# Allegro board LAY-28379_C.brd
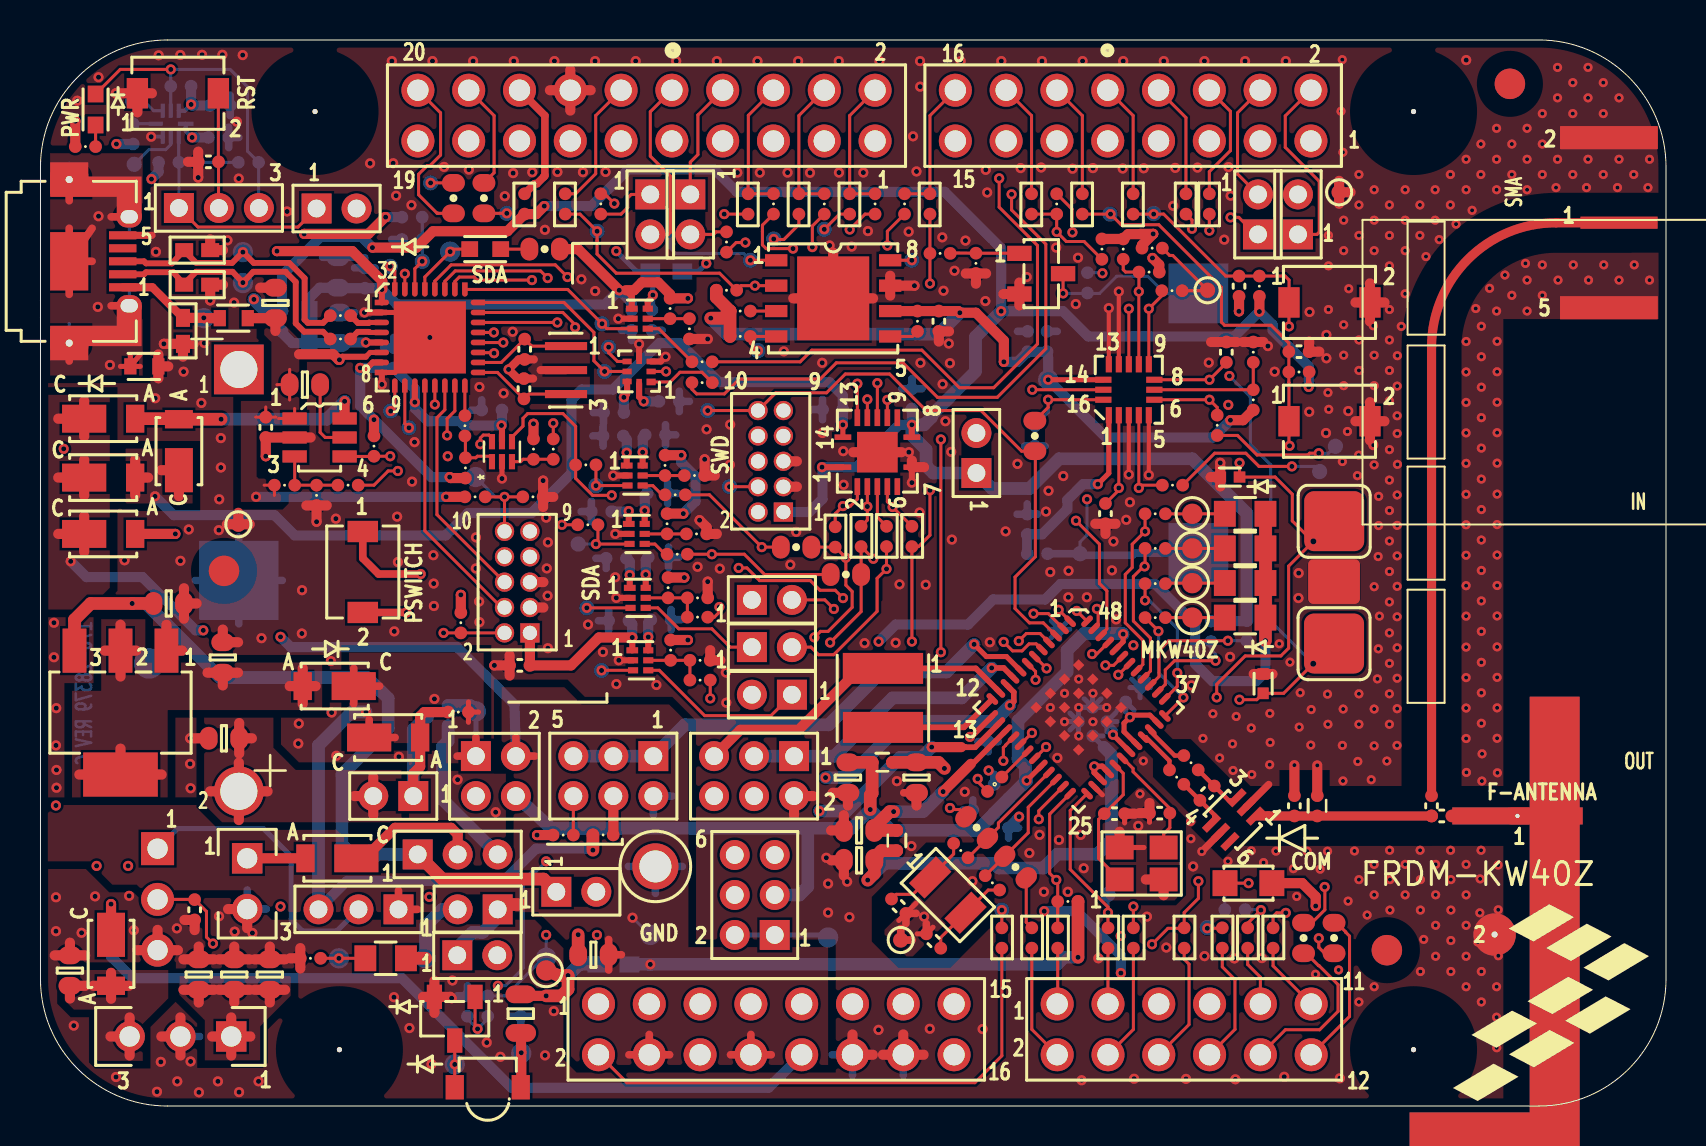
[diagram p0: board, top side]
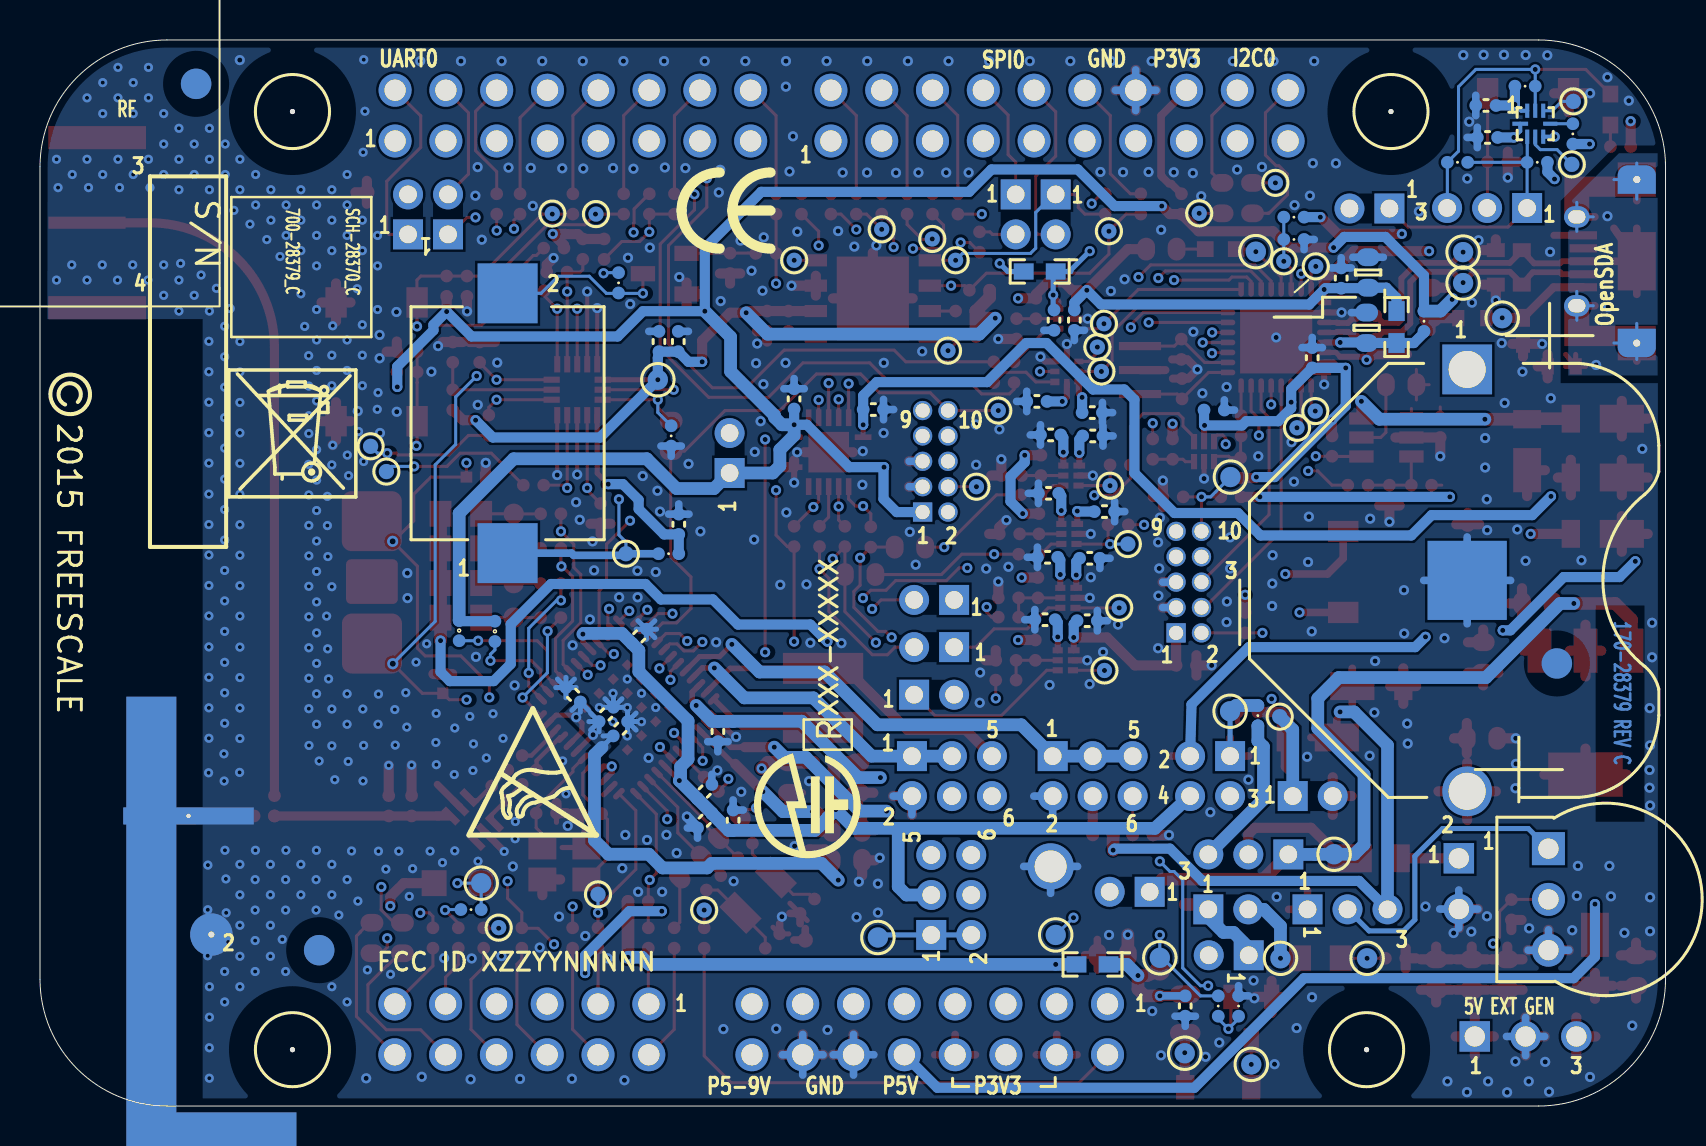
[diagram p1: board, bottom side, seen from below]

Outline 81.28 x 53.34 mm; copper layers: TOP, GND, INT_1, BOTTOM. Coordinates in mm from the lower left corner of the outline.
Outline path: 0,46.99 arc(1.86,51.48) 6.35,53.34 74.93,53.34 arc(79.42,51.48) 81.28,46.99 81.28,6.35 arc(79.42,1.86) 74.93,0 6.35,0 arc(1.86,1.86) 0,6.35 0,46.99

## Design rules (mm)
net group BALUN_100: nets N20694234 N20694236
net group RF: nets RF_N RF_P
net group USB_SI_CONN_D: nets N20299169 N20299247
net group USB_SI_D: nets SDA_USB_DN SDA_USB_DP
net group CLOCKS: nets SDA_EXTAL SWD_CLK_TGTMCU SWD_CLK_TGTMCU_BUF
net group POW: nets P5V0_SDA_USB_CONN_VBUS
nets with their own width: min track width 0.508; nets GND P3V3_SDA P5-9V_VIN P5-9V_VIN_VR

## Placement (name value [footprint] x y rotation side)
ANT1  F_Antenna  [F_ANTENNA_DIG528-2]  73.85 14.51 270 top
BT500  3003  [BATT_21X20MM]  9.92 36.86 270 bottom
BZ500  AST1109MLTRQ  [BUZZER_9P3X11P3_SMT]  57.9 34.16 0 bottom
C1  1000pF  [CC0402_25]  8.39 47.24 180 top
C2  1000pF  [CC0402_25]  59.93 41.02 270 top
C3  10uF  [CC0603_OV]  11.75 40.18 90 top
C6  0.1UF  [CC0402_25]  44.92 39.27 270 top
C9  1000pF  [CC0402_25]  62.93 37.74 0 top
C10  22PF  [CC0402_25]  24.21 37.86 270 top
C11  0.1UF  [CC0402_25]  59.3 37.72 90 top
C13  18PF  [CC0603_OV]  13.22 36.09 0 top
C15  22PF  [CC0402_25]  24.17 35.89 90 top
C21  0.1UF  [CC0402_25]  11.26 33.96 270 top
C22  0.1UF  [CC0402_25]  53.25 29.64 270 top
C25  10uF  [CC0603_OV]  6.41 25.15 0 top
C27  10uF  [CC0603_OV]  9.12 22.44 90 top
C31  0.1UF  [CC0402_25]  23.96 22.05 180 top
C32  1000pF  [CC0402_25]  7.71 9.82 270 top
C33  1.8pF  [CC0402_25]  62.7 15.02 90 top
C34  10PF  [CC0402_25]  69.56 15.02 90 top
C39  10uF  [CC0603_OV]  40.37 16.43 270 top
C40  10PF  [CC0402_25]  70.07 14.51 0 top
C41  11pF  [CC0402_25]  55.96 14.65 180 top
C42  0.6PF  [CC0402_25]  58.33 15.65 225 top
C43  10uF  [CC0603_OV]  9.17 18.4 180 top
C44  11pF  [CC0402_25]  53.7 14.63 0 top
C45  10uF  [CC0603_OV]  40.93 13.79 180 top
C46  12PF  [CC0402_25]  42.91 10 315 top
C47  12PF  [CC0402_25]  44.66 8.26 135 top
C48  2.2uF  [CC0603_OV]  27.65 7.57 180 top
C49  0.1UF  [CC0402_25]  24.02 5 270 bottom
C50  10uF  [CC0603_OV]  7.91 6.58 90 top
C51  10uF  [CC0603_OV]  9.69 6.58 90 top
C52  10uF  [CC0603_OV]  11.47 6.58 90 top
C53  10uF  [CC0603_OV]  1.47 6.78 90 top
C54  10uF  [CC0603_OV]  40.93 12.29 180 top
C55  10uF  [CC0603_OV]  43.8 16.43 270 top
C500  0.1UF  [CC0402_25]  8.98 50.06 0 bottom
C501  0.1UF  [CC0402_25]  8.9 48.46 0 bottom
C502  10uF  [CC0603_OV]  14.87 41.71 90 bottom
C503  0.1UF  [CC0402_25]  30.58 39.32 270 bottom
C504  0.1UF  [CC0402_25]  16.22 41.43 90 bottom
C505  0.1UF  [CC0402_25]  29.56 39.32 270 bottom
C506  2.2uF  [CC0603_OV]  14.95 38.94 90 bottom
C507  0.1UF  [CC0402_25]  50.33 38.25 90 bottom
C508  4.7uF  [CC0402_25]  49.36 38.25 90 bottom
C509  1uF  [CC0402_25]  17.67 37.44 90 bottom
C510  0.1UF  [CC0402_25]  43.57 35.38 90 bottom
C511  0.1UF  [CC0402_25]  31.43 35.26 0 bottom
C512  0.1UF  [CC0402_25]  39.61 34.85 180 bottom
C513  0.1UF  [CC0402_25]  22.57 34.82 180 bottom
C514  0.1UF  [CC0402_25]  28.66 34.7 180 bottom
C515  0.1UF  [CC0402_25]  30.75 33.58 0 bottom
C516  0.1UF  [CC0402_25]  28.64 33.53 180 bottom
C517  0.1UF  [CC0402_25]  30.85 30.66 0 bottom
C518  0.1UF  [CC0402_25]  28.05 29.74 180 bottom
C519  0.1UF  [CC0402_25]  49.34 29.11 90 bottom
C520  0.1UF  [CC0402_25]  30.9 27.46 0 bottom
C521  0.1UF  [CC0402_25]  28.79 27.41 180 bottom
C522  0.1UF  [CC0402_25]  31.03 24.33 0 bottom
C523  0.1UF  [CC0402_25]  28.92 24.28 180 bottom
C524  0.1UF  [CC0402_25]  51.32 23.5 135 bottom
C525  12PF  [CC0402_25]  52.26 18.88 135 bottom
C526  12PF  [CC0402_25]  54.62 20.58 45 bottom
C527  12PF  [CC0402_25]  52.97 19.59 135 bottom
C528  0.1UF  [CC0402_25]  48.04 15.73 135 bottom
C529  0.1UF  [CC0402_25]  46.62 14.3 90 bottom
C530  0.1UF  [CC0402_25]  48.04 14.27 315 bottom
C531  1uF  [CC0402_25]  47.38 18.74 270 bottom
D1  RED  [LED_0603]  2.76 49.86 90 top
D2  LED GREEN  [LED_0603]  22.24 42.88 180 top
D3  DFLS130L-7  [POWERDI-123_3MMX2MM]  3.04 34.39 0 top
D4  DFLS130L-7  [POWERDI-123_3MMX2MM]  6.92 32.66 90 top
D5  DFLS130L-7  [POWERDI-123_3MMX2MM]  3.04 31.45 0 top
D6  DFLS130L-7  [POWERDI-123_3MMX2MM]  3.04 28.63 0 top
D7  DFLS130L-7  [POWERDI-123_3MMX2MM]  14.81 21.01 180 top
D8  DFLS130L-7  [POWERDI-123_3MMX2MM]  17.29 18.44 0 top
D9  DFLS130L-7  [POWERDI-123_3MMX2MM]  14.95 12.4 180 top
D10  DFLS130L-7  [POWERDI-123_3MMX2MM]  3.53 7.72 270 top
D11  VSMB2948SL  [LED_RA_2P5X2P75_SM]  22.36 0.94 0 top
J1  CON_2x8_0.1"  [MTCONN_JT254F-D180-850-208-10D]  63.53 48.29 180 top
J2  CON_2x10_0.1"  [MTCONN_JT254F-D180-850-210-10D]  41.73 48.29 180 top
J3  CON_2x8_0.1"  [MTCONN_JT254F-D180-850-208-10D]  27.9 5.11 0 top
J4  CON_2x6_0.1"  [MTCONN_JT254F-D180-850-206-10D]  50.84 5.11 0 top
J5  SMA  [CON_SMA_EDGE_062]  78.93 44.2 90 top
J6  USB_MICRO_AB  [CON_MICROAB_10F_25_SM_RA]  1.54 42.27 0 top
J8  HDR_2X1  [HDR102_2MM]  46.8 31.67 270 top
J9  HDR 2X5  [HDR_5X2_FTSH_TH_NSP]  37.15 29.72 180 top
J11  HDR 2X5  [HDR_5X2_FTSH_TH_NSP]  24.47 23.67 180 top
J12  HDR 1X2  [SH_HDR102_2MM_BOTTOM]  35.57 25.32 180 top
J13  HDR 1X2  [SH_HDR102_2MM_BOTTOM]  35.57 22.96 180 top
J14  HDR 1X2  [SH_HDR102_2MM_BOTTOM]  37.57 20.58 0 top
J15  HDR_1X3  [HDR103_78MIL]  17.9 9.84 0 top
J16  HDR 2X3  [HDR203_TMM]  30.65 17.51 180 top
J17  HDR 2X3  [HDR203_TMM]  37.68 17.51 180 top
J18  HDR 2X2  [HDR202_TMM]  21.77 17.51 270 top
J19  HDR 1X2 TH  [HDR102]  10.34 12.4 0 top
J20  HDR_2X1  [HDR102_2MM]  22.86 9.84 0 top
J21  HDR_2X1  [HDR102_2MM]  20.84 7.54 180 top
J22  HDR 2X3  [HDR203_TMM]  36.72 8.56 90 top
J23  HDR_1X3  [HDR103_78MIL]  18.86 12.59 180 top
J24  HDR_1X3  [HDR103_78MIL]  6.92 44.93 180 top
J25  HDR 1X2  [SH_HDR102_2MM_BOTTOM]  13.8 44.91 180 top
J26  HDR_1X3  [HDR103]  9.54 3.48 270 top
J27  HDR_2X1  [HDR102_2MM]  18.64 15.51 0 top
J28  HDR_2X1  [HDR102_2MM]  32.49 45.61 90 top
J29  HDR_2X1  [HDR102_2MM]  30.49 45.61 90 top
J30  HDR_2X1  [HDR102_2MM]  62.88 43.61 270 top
J31  HDR_2X1  [HDR102_2MM]  60.88 43.61 270 top
J33  HDR_2X1  [HDR102_2MM]  25.79 10.72 180 top
L1  330 OHM  [IND_1608]  9.66 39.42 0 top
L2  330 OHM  [IND_1608]  5.19 37.01 0 top
L3  10uH  [IND_VLS4012E]  42.13 20.42 270 top
L4  2.4nH  [IND_0402]  63.84 15.02 90 top
L5  10nH  [IND_0402]  42.09 17.2 0 top
L6  10nH  [IND_0402]  42.81 13.28 270 top
LED1  RED  [LED2_0805]  60.24 29.63 90 top
LED2  RED  [LED2_0805]  60.24 27.9 90 top
LED3  RED  [LED2_0805]  60.24 26.17 90 top
LED4  RED  [LED2_0805]  60.24 24.44 90 top
LED5  BLUE  [LED2_2P34_2P1X1P25]  60.4 11.15 0 top
LED6  GREEN  [LED2_0805]  17.26 7.39 90 top
NOREF  -  []  52.33 15.63 90 top
NOREF#2  -  []  4.46 3.48 0 top
NOREF#3  -  []  -381.97 185.27 0 top
NOREF#4  -  []  62.55 28.51 90 top
NOREF#5  -  []  54.92 37.11 0 top
NOREF#6  -  []  5.79 48.52 0 top
NOREF#7  -  []  47.6 20.37 0 top
NOREF#8  -  []  79.81 7.46 0 top
NOREF#9  -  []  50.49 20.65 90 top
NOREF#10  -  []  6.52 48.5 0 top
NOREF#11  -  []  52.33 15.63 90 top
NOREF#12  -  []  6.71 48.53 90 top
NOREF#13  -  []  50.49 20.65 90 top
NOREF#14  -  []  -16.59 -36.7 0 top
NOREF#15  -  []  -408 -339.88 0 top
NOREF#16  -  []  46.96 19.94 0 top
NOREF#17  -  []  46.96 19.94 0 top
NOREF#18  -  []  51.91 14.99 90 top
NOREF#19  -  []  341.11 -159.27 0 top
NOREF#20  -  []  51.91 14.99 90 top
NOREF#21  -  []  48.3 18.81 0 top
NOREF#22  -  []  70.32 0.01 90 top
NOREF#23  -  []  42.13 18.95 90 top
NOREF#24  -  []  40.46 18.37 90 top
NOREF#25  -  []  52.69 15.98 90 top
NOREF#26  -  []  22.36 0.36 90 top
NOREF#27  -  []  24.01 0.94 90 top
NOREF#28  -  []  -36.81 -140.12 90 top
NOREF#29  -  []  40.07 18.75 0 top
NOREF#30  -  []  49.79 19.94 90 top
NOREF#31  -  []  70.62 0.25 0 top
NOREF#32  -  []  54.92 37.11 0 top
NOREF#33  -  []  48.3 18.81 0 top
NOREF#34  -  []  20.71 0.94 0 top
NOREF#35  -  []  57.9 27.66 90 top
NOREF#36  -  []  49.79 19.94 90 top
NOREF#37  -  []  47.6 19.52 0 top
NOREF#38  -  []  55.42 34.56 90 top
NOREF#39  -  [unnamed#2]  9.18 26.78 0 top
NOREF#40  -  [unnamed#2]  73.47 51.15 0 top
NOREF#41  -  []  6.12 48.5 90 top
NOREF#42  -  []  32.33 11.99 0 top
NOREF#43  -  []  62.55 39.81 0 top
NOREF#44  -  []  52.92 31.34 0 top
NOREF#45  -  []  47.6 19.52 0 top
NOREF#46  -  []  47.6 20.37 0 top
NOREF#47  -  []  4.46 3.48 0 top
NOREF#48  -  []  55.42 34.56 90 top
NOREF#49  -  []  52.92 31.35 0 top
NOREF#50  -  []  4.46 3.48 0 top
NOREF#51  -  []  51.48 15.63 90 top
NOREF#52  -  []  53.42 37.11 0 top
NOREF#53  -  []  318.09 -153.04 0 top
NOREF#54  -  []  0 41.47 0 top
NOREF#55  -  []  52.69 15.98 90 top
NOREF#56  -  []  55.69 35.34 90 top
NOREF#57  -  [unnamed#2]  67.32 7.8 0 top
NOREF#58  -  []  78.89 16.29 0 top
NOREF#59  -  []  151.38 59.85 0 top
NOREF#60  -  []  -36.81 -113.45 0 top
NOREF#61  -  []  51.48 15.63 90 top
NOREF#62  -  []  21.11 0.41 0 top
NOREF#63  -  []  53.14 36.34 0 top
NOREF#64  -  []  55.92 31.34 90 top
NOREF#65  -  []  345 -146.74 0 top
NOREF#66  -  []  -71.81 -129.47 0 top
NOREF#67  -  [unnamed#2]  13.73 49.76 180 bottom
NOREF#68  -  [unnamed#2]  73.47 51.15 180 bottom
NOREF#69  -  []  225.55 -29.24 90 bottom
NOREF#70  -  []  74.49 -17.35 0 bottom
NOREF#71  -  [unnamed#2]  67.32 7.8 180 bottom
NOREF#72  -  []  40.28 12.4 90 bottom
NOREF#73  -  []  91.82 39.52 180 bottom
NOREF#74  -  [unnamed#2]  68.66 49.76 180 bottom
NOREF#75  -  []  106.28 -52.14 270 bottom
NOREF#76  -  []  54.61 5.51 180 bottom
NOREF#77  -  [unnamed#2]  14.95 2.82 180 bottom
NOREF#78  -  []  77.85 10.86 180 bottom
NOREF#79  -  [unnamed#2]  5.43 22.14 180 bottom
NOREF#80  -  []  54.66 12.88 180 bottom
NOREF#81  -  []  85.94 -20.8 180 bottom
NOREF#82  -  [unnamed#2]  68.66 2.82 180 bottom
NOREF#83  -  []  47.36 44.81 90 bottom
NOREF#84  -  []  71.84 30.48 180 bottom
Q1  MMBT3904LT1G  [SOT23]  50.04 41.65 270 top
Q2  MMBT3904LT1G  [SOT23]  20.71 4.37 180 top
R1  100  [RC0402_25]  2.25 48.01 0 top
R3  0  [RC0402_25]  39.19 45.14 90 top
R4  0  [RC0402_25]  41.73 45.14 90 top
R5  0  [RC0402_25]  43.21 45.14 90 top
R7  0  [RC0402_25]  50.81 45.14 270 top
R8  0  [RC0402_25]  36.65 45.14 90 top
R10  220  [RC0603_OV]  25.21 42.88 180 top
R12  4.7K  [RC0402_25]  44.98 42.66 0 top
R13  10.0K  [RC0402_25]  54.14 42.88 270 top
R14  47K  [RC0402_25]  46.77 42.16 270 top
R16  10.0K  [RC0402_25]  34.3 40.82 0 top
R17  10.0K  [RC0402_25]  60.95 41.02 90 top
R18  0  [RC0402_25]  56.58 40.79 0 top
R19  4.7K  [RC0402_25]  31.48 39.9 270 top
R20  10.0K  [RC0402_25]  34.99 39.78 0 top
R21  33  [RC0402_25]  15 39.55 0 top
R22  10.0K  [RC0402_25]  43.85 39.27 90 top
R23  10.0K  [RC0402_25]  32.45 38.89 270 top
R24  10.0K  [RC0402_25]  34.99 38.51 0 top
R25  33  [RC0402_25]  15 38.38 0 top
R26  10.0K  [RC0402_25]  62.93 36.73 180 top
R27  1K  [RC0402_25]  33.08 37.24 0 top
R28  1K  [RC0402_25]  33.08 36.2 180 top
R29  10.0K  [RC0402_25]  60.64 35.33 90 top
R30  0  [RC0402_25]  58.84 34.06 270 top
R31  0  [RC0402_25]  21.22 34.04 90 top
R32  0  [RC0603_OV]  49.72 33.53 270 top
R33  10.0K  [RC0402_25]  16.68 33.02 270 top
R34  10.0K  [RC0402_25]  24.65 32.87 90 top
R35  0  [RC0402_25]  25.64 32.87 90 top
R36  0  [RC0402_25]  27.27 32.08 0 top
R37  4.7K  [RC0402_25]  31.23 32.05 270 top
R38  10.0K  [RC0402_25]  21.25 31.93 90 top
R39  10.0K  [RC0402_25]  32.7 31.55 0 top
R40  10.0K  [RC0402_25]  12.2 31.06 0 top
R41  1K  [RC0402_25]  15.38 31.06 180 top
R42  0  [RC0402_25]  56.6 31.06 0 top
R43  1K  [RC0402_25]  31.74 30.58 0 top
R44  15K  [RC0402_25]  13.8 30.56 270 top
R45  0  [RC0603_OV]  63.16 8.41 270 top
R46  4.7K  [RC0402_25]  21.73 30.48 0 top
R47  10.0K  [RC0402_25]  24.63 30.48 0 top
R48  330  [RC0402_25]  55.74 29.63 180 top
R49  4.7K  [RC0402_25]  31.33 29.13 270 top
R50  0  [RC0402_25]  27.37 29.08 0 top
R51  10.0K  [RC0402_25]  32.8 28.63 0 top
R52  0  [RC0603_OV]  37.78 27.97 0 top
R53  330  [RC0402_25]  55.74 27.9 180 top
R54  0  [RC0603_OV]  64.68 8.41 270 top
R55  1K  [RC0402_25]  31.84 27.61 0 top
R56  0  [RC0603_OV]  40.27 26.59 0 top
R57  330  [RC0402_25]  55.74 26.14 180 top
R59  4.7K  [RC0402_25]  31.38 25.93 270 top
R60  10.0K  [RC0402_25]  32.85 25.43 0 top
R61  0  [RC0402_25]  32.85 24.46 180 top
R62  330  [RC0402_25]  55.74 24.44 180 top
R63  10.0K  [RC0402_25]  21.02 24.18 270 top
R64  4.7K  [RC0402_25]  31.51 22.81 270 top
R65  10.0K  [RC0402_25]  32.98 22.3 0 top
R66  0  [RC0402_25]  32.98 21.31 180 top
R67  5K  [POT3_3352T]  5.85 12.88 270 bottom
R68  0  [RC0402_25]  47.71 16.1 225 top
R69  0  [RC0402_25]  57.53 17.18 315 top
R70  0  [RC0402_25]  56.81 16.46 315 top
R71  0  [RC0603_OV]  46.81 13.93 315 top
R72  0  [RC0402_25]  28.13 13.56 0 top
R73  0  [RC0402_25]  20.89 19.71 0 top
R74  0  [RC0402_25]  46.02 12.78 135 top
R75  0  [RC0402_25]  20.38 19.53 90 bottom
R76  0  [RC0603_OV]  48.75 11.96 315 top
R77  0  [RC0402_25]  47.6 11.17 315 top
R78  0  [RC0402_25]  51.37 10.24 180 top
R79  27K  [RC0402_25]  21.35 5 90 bottom
R80  1.5K  [RC0402_25]  22.36 5 270 bottom
R81  330  [RC0402_25]  13.5 7.39 180 top
R82  18.2  [RC0805_OV]  24.02 4.62 270 top
R83  0  [RC0402_25]  28.02 45.14 270 top
R84  0  [RC0402_25]  34.3 43.23 90 top
R85  102K  [RC0402_25]  26.14 13.56 180 top
R87  0  [RC0603_OV]  22.17 45.43 90 top
R88  0  [RC0603_OV]  20.65 45.43 90 top
R500  180K  [RC0402_25]  7.02 51.03 180 bottom
R501  4.7K  [RC0402_25]  4.64 48.64 270 bottom
R502  0  [RC0402_25]  10.4 47.22 0 bottom
R503  10.0K  [RC0402_25]  6.41 47.22 0 bottom
R504  4.7K  [RC0402_25]  18.58 44.48 0 bottom
R505  10.0K  [RC0402_25]  18.58 43.36 180 bottom
R506  10.0K  [RC0402_25]  49.72 33.53 270 bottom
R507  0  [RC0402_25]  49.85 27.64 0 bottom
R508  10.0K  [RC0402_25]  60.32 23.79 270 bottom
R509  10.0K  [RC0402_25]  58.53 23.75 270 bottom
R510  10.0K  [RC0402_25]  53.07 42.88 270 top
R511  330  [RC0402_25]  59.73 9.83 0 bottom
R512  1K  [RC0402_25]  52.35 41.19 270 bottom
R513  10.0K  [RC0402_25]  55.59 42.93 0 top
SH3  0  [SH0402]  24.21 45.14 90 top
SH4  0  [SH0402]  26.24 45.14 90 top
SH7  0  [SH0402]  35.38 45.14 90 top
SH8  0  [SH0402]  37.92 45.14 90 top
SH9  0  [SH0402]  40.46 45.14 90 top
SH10  0  [SH0402]  44.48 45.14 90 top
SH11  0  [SH0402]  49.56 45.14 90 top
SH12  0  [SH0402]  52.1 45.14 90 top
SH13  0  [SH0402]  54.64 45.14 90 top
SH14  0  [SH0402]  57.28 45.14 90 top
SH15  0  [SH0402]  58.45 45.14 90 top
SH18  0  [RC0402_25]  55.43 41.73 0 top
SH19  0  [RC0402_25]  60.64 37.72 90 top
SH20  0  [SH0402]  41.03 28.5 270 top
SH21  0  [SH0402]  42.3 28.5 270 top
SH22  0  [SH0402]  43.57 28.5 270 top
SH23  0  [SH0402]  39.74 28.47 270 top
SH24  0  [SH0402]  48.07 8.41 270 top
SH25  0  [SH0402]  49.57 8.41 270 top
SH26  0  [SH0402]  50.86 8.41 270 top
SH27  0  [SH0402]  53.38 8.41 270 top
SH28  0  [SH0402]  54.65 8.41 270 top
SH29  0  [SH0402]  57.19 8.41 270 top
SH30  0  [SH0402]  59.09 8.41 270 top
SH31  0  [SH0402]  60.36 8.41 270 top
SH33  0  [SH0402]  61.63 8.41 270 top
SH500  0  [SH0603]  31.29 41.76 0 bottom
SH501  0  [SH0603]  13.45 38.98 270 bottom
SH502  0  [RC0402_25]  12.08 39.27 90 bottom
SH503  0  [SH0603]  28.65 7.09 0 bottom
SW1  3x3mm  [ELECTRODE_SQ_3MM]  64.68 23.14 0 top
SW2  3x3mm  [ELECTRODE_SQ_3MM]  64.69 29.26 0 top
SW3  TL1015AF160QG  [SW2_SPST_4X3_SM]  64.45 34.26 0 top
SW4  TL1015AF160QG  [SW2_SPST_4X3_SM]  64.45 40.21 0 top
SW5  TL1015AF160QG  [SW2_SPST_4X3_SM]  16.12 26.72 270 top
SW6  TL1015AF160QG  [SW2_SPST_4X3_SM]  6.87 50.67 0 top
TP2  -  [TPAD_030]  64.94 45.72 0 top
TP3  -  [TPAD_040]  10.12 42.73 180 bottom
TP4  -  [TPAD_040]  10.12 41.18 180 bottom
TP14  -  [TPAD_030]  58.36 40.82 270 top
TP19  -  [TPAD_030]  64.75 33.01 270 bottom
TP20  -  [TPAD_030]  63.96 31.74 270 bottom
TP21  -  [TPAD_040]  57.59 29.63 180 top
TP22  -  [TPAD_030]  9.89 29.11 0 top
TP25  -  [TPAD_040]  57.59 27.9 270 top
TP26  -  [TPAD_040]  57.59 26.16 270 top
TP28  -  [TPAD_040]  57.59 24.44 180 top
TP29  -  [TPAD_030]  19.29 19.48 180 bottom
TP30  -  [TPAD_040]  21.77 19.75 0 bottom
TP31  TESTLOOP_BLACK  [TP_TH_063]  30.75 11.99 0 top
TP36  -  [TPAD_030]  43.01 8.31 0 top
TP500  -  [TPAD_030]  4.61 50.27 0 bottom
TP501  -  [TPAD_030]  4.69 47.12 0 bottom
TP502  -  [TPAD_030]  55.66 44.65 180 bottom
TP503  -  [TPAD_030]  53.48 44.63 180 bottom
TP504  -  [TPAD_030]  27.83 43.77 0 bottom
TP505  -  [TPAD_030]  39.19 43.87 180 bottom
TP506  -  [TPAD_030]  36.66 43.38 180 bottom
TP507  -  [TPAD_040]  20.49 42.75 180 bottom
TP508  -  [TPAD_030]  43.57 42.32 0 bottom
TP509  -  [TPAD_030]  35.5 42.32 0 bottom
TP510  -  [TPAD_030]  19.09 42.27 180 bottom
TP511  -  [TPAD_030]  17.49 42.01 0 bottom
TP513  -  [TPAD_040]  8.17 39.42 180 bottom
TP514  -  [TPAD_030]  28.08 39.14 180 bottom
TP515  -  [TPAD_030]  28.41 37.97 0 bottom
TP516  -  [TPAD_030]  35.88 37.8 0 bottom
TP517  -  [TPAD_030]  28.21 36.75 0 bottom
TP518  -  [TPAD_040]  50.39 36.34 270 bottom
TP519  -  [TPAD_030]  33.36 34.8 90 bottom
TP520  -  [TPAD_030]  17.51 34.77 180 bottom
TP521  -  [TPAD_030]  18.43 33.93 180 bottom
TP522  -  [TPAD_030]  27.77 31.04 180 bottom
TP523  -  [TPAD_030]  34.46 30.99 180 bottom
TP524  -  [TPAD_040]  21.76 31.47 180 bottom
TP525  -  [TPAD_030]  26.89 28.12 180 bottom
TP526  -  [TPAD_030]  51.98 27.64 180 bottom
TP528  -  [TPAD_030]  27.32 24.93 180 bottom
TP529  -  [TPAD_030]  28.05 21.79 180 bottom
TP530  -  [TPAD_040]  16.57 12.6 180 bottom
TP531  -  [TPAD_040]  59.22 11.15 180 bottom
TP532  -  [TPAD_030]  53.38 10.59 180 bottom
TP533  -  [TPAD_040]  39.38 8.43 180 bottom
TP534  -  [TPAD_040]  30.49 8.56 180 bottom
TP535  -  [TPAD_040]  25.29 7.42 180 bottom
TP536  -  [TPAD_040]  19.25 7.39 0 bottom
TP537  -  [TPAD_040]  14.92 7.39 0 bottom
TP538  -  [TPAD_040]  24.04 2.64 180 bottom
TP539  -  [TPAD_040]  20.71 2.08 180 bottom
TP540  -  [TPAD_030]  23.32 44.67 180 bottom
TP541  -  [TPAD_030]  58.34 8.93 180 bottom
TP542  -  [TPAD_030]  19.51 46.19 180 bottom
TP543  -  [TPAD_030]  48.07 9.8 180 bottom
TP544  -  [TPAD_040]  25.29 6.78 90 top
TVS1  PGB2010402KRHF  [DIODE_0402]  59.47 31.47 180 top
TVS2  PGB2010402KRHF  [DIODE_0402]  61.14 21.13 90 top
U1  0402ESDA-MLP  [0402_MLP]  7.84 42.82 0 top
U2  0402ESDA-MLP  [0402_MLP]  7.84 41.1 0 top
U4  AT45DB021E  [DFN8_1P27_6X5MM_3P6X4P2]  39.64 40.41 0 top
U5  74LVCH1T45  [UDFN6_1X1P5MM]  29.98 39.4 0 top
U6  0402ESDA-MLP  [0402_MLP]  7.12 38.79 270 top
U7  MK20DX128VFM5  [QFN32_S142EP]  19.47 38.46 0 top
U8  74LVC2T45GM,125  [QFN8_1P6X1P6MM]  29.93 36.75 180 top
U9  FXOS8700CQ  [QFN5X3_0P5_3X3]  54.42 35.84 90 top
U10  MIC2005-0.8YM6  [SOT23-6_A]  13.96 33.45 0 top
U11  NLX2G14  [UDFN6_1P45X1_0P5MM]  23.08 32.74 90 top
U12  TXB0104  [QFN14_RGY]  41.85 32.72 0 top
U13  74LVCH1T45  [UDFN6_1X1P5MM]  29.73 31.55 0 top
U14  74LVCH1T45  [UDFN6_1X1P5MM]  29.83 28.63 0 top
U15  74LVCH1T45  [UDFN6_1X1P5MM]  29.88 25.43 0 top
U16  74LVCH1T45  [UDFN6_1X1P5MM]  30.01 22.3 0 top
U17  NCP1117ST33T3G  [SOT223]  4 19.69 180 top
U18  MKW40Z160VHT4  [MAPLGA64_7X7_0P5MM]  51.91 19.94 315 top
U500  NTSX2102GU8H  [XQFN8_1P45X1P25MM]  6.52 49.15 180 bottom
X1  8.00MHZ  [XTAL3_3P35X1P45_SM]  26.28 36.82 90 top
Y1  32MHZ  [XTLOSC4_3P2X2P5MM_SM]  55.06 12.14 0 top
Y2  32.768KHZ  [XTAL2-3P2X1P5-SM]  45.37 10.56 315 top
Z1  50/100 OHMS  [XFMR6_0P65_2X1]  59.65 14.33 135 top

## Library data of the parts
ANT1 = F_Antenna
BT500 = BATTERY_SKT_3V
BZ500 = BUZZER_PIEZO
C1 C2 C9-C11 C15 C22 C32 C33 C39 C41 C42 C44-C48 C50-C55 C506-C509 C525-C527 C531 = CAP_NP
C3 C6 C21 C25 C27 C31 C43 C49 C500-C505 C510-C524 C528-C530 = CAP_NP: tolerance: 10%
C13 C34 C40 = CAP_NP: tolerance: 5%
D1 D2 D11 LED1-LED6 = LED
D3-D10 = DIODE_SCHTKY
J1 J3 = CONN_2x8_MTCONN
J2 = CONN_2x10_MTCONN
J4 = CONN_2x6_MTCONN
J5 = SMB
J6 = MICRO_USB_CONN_10PIN
J8 J12-J14 J19-J21 J25 J27-J31 J33 = CONN_HDR_2X1
J9 J11 = CONN_HDR_5X2
J15 J23 J24 J26 = CONN_HDR_3X1
J16 J17 J22 = CONN_HDR_3X2
J18 = CONN_HDR_2X2
L1 L2 = BEAD
L3 = IND_FERRITE
L4-L6 = INDUCTOR
Q1 Q2 = NPN
R1 R13 R16 R17 R19 R20 R22 R24 R26 R29 R33 R37 R40 R44 R46 R49 R59 R64 R501 R504 R506 R508-R510 R513 = RES: tolerance: 1%
R3-R5 R7 R8 R10 R12 R14 R18 R21 R25 R27 R28 R30-R32 R35 R36 R41-R43 R45 R47 R48 R50 R52-R57 R61-R63 R66 R68-R85 R87 R88 R500 R505 R507 R511 R512 SH18 SH19 SH502 = RES
R23 R34 R38 R39 R51 R60 R65 R502 R503 = RES: tolerance: 5%
R67 = POT
SH3 SH4 SH7-SH15 SH20-SH31 SH33 SH500 SH501 SH503 = RES_SHORT-2
SW1 SW2 = ELECTRODE
SW3-SW6 = SW_SPNO_2P
TP2 TP14 TP19 TP20 TP22 TP29 TP31 TP36 TP500-TP506 TP508-TP511 TP514-TP517 TP519-TP523 TP525 TP526 TP528 TP529 TP532 TP540-TP543 = TESTLOOP
TP3 TP4 TP21 TP25 TP26 TP28 TP30 TP507 TP513 TP518 TP524 TP530 TP531 TP533-TP539 TP544 = TestLoop
TVS1 TVS2 U1 U2 U6 = DIODE_TVS_BIDIR
U4 = AT45DB021E_9P
U5 U13-U16 = 74LVCH1T45_6P
U7 = PK20DX128V_QFN_32P
U8 = 74LVC2T45GM_8P
U9 = FXOS8700CQ_QFN_16P
U10 = MIC2005-0.8YM6
U11 = NLU2GU04
U12 = TXB0104
U17 = LD1117AS18
U18 = MKW40Z160_MAPLGA64
U500 = NTSX2102GU8H_8P
X1 = XTAL_CS
Y1 = XTAL_13Y
Y2 = CRYSTAL
Z1 = 2450BL

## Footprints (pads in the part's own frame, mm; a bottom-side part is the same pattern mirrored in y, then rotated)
0402_MLP
  rect 0.9x0.7 smd: 1(-0.65,0) 2(0.65,0)
BATT_21X20MM
  rect 2.489x2.489 hole 1.854: 1(0,0)
  round 2.489 hole 1.854: 2(21.11,0)
  rect 3.96x3.96 smd: 3(10.555,0)
BUZZER_9P3X11P3_SMT
  rect 3x3 smd: 1(0,6.5) 2(0,-6.5)
CC0402_25
  round 0.635 smd: 1(-0.508,0) 2(0.508,0)
CC0603_OV
  oval 0.889x1.143 smd: 1(-0.762,0) 2(0.762,0)
CON_MICROAB_10F_25_SM_RA
  rect 1.372x0.406 smd: 1(2.575,-1.3) 2(2.575,-0.65) 3(2.575,0) 4(2.575,0.65) 5(2.575,1.3)
  oval 1.27x1.067 hole 0.864x0.66: 6(2.9,2.225) 7(2.9,-2.225)
  rect 1.905x2.921 smd: 8(-0.1,0)
  custom 0.356x0.356 hole 1.524x0.838: 9(-0.1,4.09) 10(-0.1,-4.09)
CON_SMA_EDGE_062
  rect 0.61x3.861 smd: 1(0,0)
  rect 1.143x4.877 smd: 2(4.255,0.508) 3(4.255,0.508) 4(-4.255,0.508) 5(-4.255,0.508)
DFN8_1P27_6X5MM_3P6X4P2
  rect 1.118x0.61 smd: 1(-2.85,1.905) 2(-2.85,0.635) 3(-2.85,-0.635) 4(-2.85,-1.905) 5(2.85,-1.905) 6(2.85,-0.635) 7(2.85,0.635) 8(2.85,1.905)
  rect 3.607x4.191 smd: 9(0,0)
DIODE_0402
  rect 0.584x0.559 smd: 1(-0.483,0) 2(0.483,0)
ELECTRODE_SQ_3MM
  custom 0.75x0.75 smd: 1(0,0)
F_ANTENNA_DIG528-2
  custom 0.212x0.212 hole 0.305: 1(0,0)
  custom 2.127x2.127 hole 0.305: 2(5.933,-1.144)
HDR102
  rect 1.524x1.524 hole 1.016: 1(0,0)
  round 1.524 hole 1.016: 2(0,-2.54)
HDR102_2MM
  rect 1.499x1.499 hole 0.889: 1(0,0)
  round 1.499 hole 0.889: 2(-2,0)
HDR103
  rect 1.524x1.524 hole 1.016: 1(0,0)
  round 1.524 hole 1.016: 2(0,-2.54) 3(0,-5.08)
HDR103_78MIL
  rect 1.499x1.499 hole 0.889: 1(0,0)
  round 1.499 hole 0.889: 2(-2,0) 3(-4,0)
HDR202_TMM
  rect 1.499x1.499 hole 0.889: 1(0,0)
  round 1.499 hole 0.889: 2(0,2) 3(2,0) 4(2,2)
HDR203_TMM
  rect 1.499x1.499 hole 0.889: 1(0,0)
  round 1.499 hole 0.889: 2(0,2) 3(2,0) 4(2,2) 5(4,0) 6(4,2)
HDR_5X2_FTSH_TH_NSP
  rect 0.965x0.965 hole 0.711: 1(0,0)
  round 0.965 hole 0.711: 2(1.27,0) 3(0,-1.27) 4(1.27,-1.27) 5(0,-2.54) 6(1.27,-2.54) 7(0,-3.81) 8(1.27,-3.81) 9(0,-5.08) 10(1.27,-5.08)
IND_0402
  round 0.635 smd: 1(-0.508,0) 2(0.508,0)
IND_1608
  rect 0.61x0.813 smd: 1(-0.7,0) 2(0.7,0)
IND_VLS4012E
  rect 1.549x4.013 smd: 1(-1.475,0) 2(1.475,0)
LED2_2P34_2P1X1P25
  rect 1.245x1.295 smd: A(1.172,0) C(-1.172,0)
LED2_0805
  rect 1.295x1.092 smd: A(0,-1.016) C(0,1.016)
LED_0603
  rect 0.838x0.787 smd: A(-0.775,0) C(0.775,0)
LED_RA_2P5X2P75_SM
  rect 0.914x1.219 smd: A(1.65,0) C(-1.65,0)
MAPLGA64_7X7_0P5MM
  oval 0.711x0.279 smd: 1(-3.35,2.75) 2(-3.35,2.25) 3(-3.35,1.75) 4(-3.35,1.25) 5(-3.35,0.75) 6(-3.35,0.25) 7(-3.35,-0.25) 8(-3.35,-0.75) 9(-3.35,-1.25) 10(-3.35,-1.75) 11(-3.35,-2.25) 12(-3.35,-2.75) 25(3.35,-2.75) 26(3.35,-2.25) 27(3.35,-1.75) 28(3.35,-1.25) 29(3.35,-0.75) 30(3.35,-0.25) 31(3.35,0.25) 32(3.35,0.75) 33(3.35,1.25) 34(3.35,1.75) 35(3.35,2.25) 36(3.35,2.75)
  oval 0.279x0.711 smd: 13(-2.75,-3.35) 14(-2.25,-3.35) 15(-1.75,-3.35) 16(-1.25,-3.35) 17(-0.75,-3.35) 18(-0.25,-3.35) 19(0.25,-3.35) 20(0.75,-3.35) 21(1.25,-3.35) 22(1.75,-3.35) 23(2.25,-3.35) 24(2.75,-3.35) 37(2.745,3.35) 38(2.25,3.35) 39(1.75,3.35) 40(1.25,3.35) 41(0.75,3.35) 42(0.25,3.35) 43(-0.25,3.35) 44(-0.75,3.35) 45(-1.25,3.35) 46(-1.75,3.35) 47(-2.25,3.35) 48(-2.75,3.35)
  rect 0.406x0.406 smd: 49(-1.5,1.5) 50(-0.5,1.5) 51(0.5,1.5) 52(1.5,1.5) 53(-1.5,0.5) 54(-0.5,0.5) 55(0.5,0.5) 56(1.5,0.5) 57(-1.5,-0.5) 58(-0.5,-0.5) 59(0.5,-0.5) 60(1.5,-0.5) 61(-1.5,-1.5) 62(-0.5,-1.5) 63(0.5,-1.5) 64(1.5,-1.5)
MTCONN_JT254F-D180-850-206-10D
  round 1.651 hole 1.067: 1(0,0) 2(0,-2.54) 3(2.54,0) 4(2.54,-2.54) 5(5.08,0) 6(5.08,-2.54) 7(7.62,0) 8(7.62,-2.54) 9(10.16,0) 10(10.16,-2.54) 11(12.7,0) 12(12.7,-2.54)
MTCONN_JT254F-D180-850-208-10D
  round 1.651 hole 1.067: 1(0,0) 2(0,-2.54) 3(2.54,0) 4(2.54,-2.54) 5(5.08,0) 6(5.08,-2.54) 7(7.62,0) 8(7.62,-2.54) 9(10.16,0) 10(10.16,-2.54) 11(12.7,0) 12(12.7,-2.54) 13(15.24,0) 14(15.24,-2.54) 15(17.78,0) 16(17.78,-2.54)
MTCONN_JT254F-D180-850-210-10D
  round 1.651 hole 1.067: 1(0,0) 2(0,-2.54) 3(2.54,0) 4(2.54,-2.54) 5(5.08,0) 6(5.08,-2.54) 7(7.62,0) 8(7.62,-2.54) 9(10.16,0) 10(10.16,-2.54) 11(12.7,0) 12(12.7,-2.54) 13(15.24,0) 14(15.24,-2.54) 15(17.78,0) 16(17.78,-2.54) 17(20.32,0) 18(20.32,-2.54) 19(22.86,0) 20(22.86,-2.54)
POT3_3352T
  rect 1.651x1.651 hole 1.016: 1(0,0)
  round 1.651 hole 1.016: 2(2.54,0) 3(5.08,0)
POWERDI-123_3MMX2MM
  rect 0.914x1.397 smd: A(1.7,0)
  rect 2.21x1.397 smd: C(-0.85,0)
QFN5X3_0P5_3X3
  rect 0.813x0.305 smd: 1(-1.275,1) 2(-1.275,0.5) 3(-1.275,0) 4(-1.275,-0.5) 5(-1.275,-1) 9(1.275,-1) 10(1.275,-0.5) 11(1.275,0) 12(1.275,0.5) 13(1.275,1)
  rect 0.305x0.813 smd: 6(-0.5,-1.275) 7(0,-1.275) 8(0.5,-1.275) 14(0.5,1.275) 15(0,1.275) 16(-0.5,1.275)
QFN8_1P6X1P6MM
  rect 0.457x0.33 smd: 1(-0.6,0.525)
  rect 0.457x0.279 smd: 2(-0.6,0) 3(-0.6,-0.5) 5(0.6,-0.5) 6(0.6,0) 7(0.6,0.5)
  rect 0.279x0.457 smd: 4(0,-0.6) 8(0,0.6)
QFN14_RGY
  rect 0.838x0.279 smd: 1(-1.725,-0.75) 7(1.725,-0.75) 8(1.725,0.75) 14(-1.725,0.75)
  rect 0.279x0.838 smd: 2(-1,-1.725) 3(-0.5,-1.725) 4(0,-1.725) 5(0.5,-1.725) 6(1,-1.725) 9(1,1.725) 10(0.5,1.725) 11(0,1.725) 12(-0.5,1.725) 13(-1,1.725)
  rect 2.032x2.032 smd: 15(0,0)
QFN32_S142EP
  custom 0.07x0.07 smd: 1(-2.4,1.751) 2(-2.4,1.251) 3(-2.4,0.751) 4(-2.4,0.25) 5(-2.4,-0.25) 6(-2.4,-0.751) 7(-2.4,-1.251) 8(-2.4,-1.751) 9(-1.751,-2.4) 10(-1.251,-2.4) 11(-0.751,-2.4) 12(-0.25,-2.4) 13(0.25,-2.4) 14(0.751,-2.4) 15(1.251,-2.4) 16(1.751,-2.4) 17(2.4,-1.751) 18(2.4,-1.251) 19(2.4,-0.751) 20(2.4,-0.25) 21(2.4,0.25) 22(2.4,0.751) 23(2.4,1.251) 24(2.4,1.751) 25(1.751,2.4) 26(1.251,2.4) 27(0.751,2.4) 28(0.25,2.4) 29(-0.25,2.4) 30(-0.751,2.4) 31(-1.251,2.4) 32(-1.751,2.4)
  rect 3.607x3.607 smd: 33(0,0)
RC0402_25
  round 0.635 smd: 1(-0.508,0) 2(0.508,0)
RC0603_OV
  oval 0.889x1.143 smd: 1(-0.762,0) 2(0.762,0)
RC0805_OV
  oval 0.889x1.524 smd: 1(-0.965,0) 2(0.965,0)
SH0402
  round 0.635 smd: 1(-0.508,0) 2(0.508,0)
SH0603
  rect 0.991x0.813 smd: 1(-0.8,0) 2(0.8,0)
SH_HDR102_2MM_BOTTOM
  rect 1.499x1.499 hole 0.889: 1(0,0)
  round 1.499 hole 0.889: 2(-2,0)
SOT23
  rect 0.762x1.219 smd: 1(-1.016,-1.092) 2(1.016,-1.092) 3(0,1.092)
SOT23-6_A
  rect 1.219x0.61 smd: 1(-1.25,0.95) 2(-1.25,0) 3(-1.25,-0.95) 4(1.25,-0.95) 5(1.25,0) 6(1.25,0.95)
SOT223
  rect 1.194x2.21 smd: 1(-2.3,-3.1) 2(0,-3.1) 3(2.3,-3.1)
  rect 3.734x2.21 smd: 4(0,3.1)
SW2_SPST_4X3_SM
  rect 1.067x1.524 smd: 1(-2.025,0) 2(2.025,0)
TP_TH_063
  round 2.311 hole 1.6: 1(0,0)
TPAD_030
  round 0.762 smd: 1(0,0)
TPAD_040
  round 1.016 smd: 1(0,0)
UDFN6_1P45X1_0P5MM
  rect 0.762x0.305 smd: 1(-0.5,0.5) 2(-0.5,0) 3(-0.5,-0.5) 4(0.5,-0.5) 5(0.5,0) 6(0.5,0.5)
UDFN6_1X1P5MM
  rect 0.584x0.305 smd: 1(-0.418,0.5)
  rect 0.508x0.305 smd: 2(-0.38,0) 3(-0.38,-0.5) 4(0.38,-0.5) 5(0.38,0) 6(0.38,0.5)
unnamed#2
  round 1.524 smd: (0,0)
XFMR6_0P65_2X1
  rect 0.356x1.016 smd: 1(-0.65,-0.9) 2(0,-0.9) 3(0.65,-0.9) 4(0.65,0.9) 5(0,0.9) 6(-0.65,0.9)
XQFN8_1P45X1P25MM
  rect 0.787x0.203 smd: 1(-0.75,0)
  rect 0.203x0.711 smd: 2(-0.4,-0.65) 3(0,-0.65) 4(0.4,-0.65) 6(0.4,0.65) 7(0,0.65) 8(-0.4,0.65)
  rect 0.711x0.203 smd: 5(0.75,0)
XTAL2-3P2X1P5-SM
  rect 1.092x1.905 smd: 1(-1.25,0) 2(1.25,0)
XTAL3_3P35X1P45_SM
  rect 0.406x2.108 smd: 1(1.2,0) 2(0,0) 3(-1.2,0)
XTLOSC4_3P2X2P5MM_SM
  rect 1.397x1.194 smd: 1(-1.1,-0.8) 2(1.1,-0.8) 3(1.1,0.8) 4(-1.1,0.8)

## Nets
GND: ANT1.2(GND) BT500.3(NEG) C1.2 C2.2 C3.2 C6.2 C9.2 C10.2 C11.2 C15.2 C21.2 C22.2 C25.2 C27.2 C31.2 C32.2 C33.2 C39.2 C41.2 C43.2 C44.2 C45.2 C46.2 C47.2 C48.2 C49.2 C50.2 C51.2 C52.2 C53.2 C54.2 C55.2 C500.2 C501.2 C502.2 C503.2 C504.2 C505.2 C506.2 C507.2 C508.2 C509.2 C510.2 C511.2 C512.2 C513.2 C514.2 C515.2 C516.2 C517.2 C518.2 C519.2 C520.2 C521.2 C522.2 C523.2 C524.2 C525.2 C526.2 C527.2 C528.2 C529.2 C530.2 C531.2 J2.14(B7) J3.12(B6) J3.14(B7) J5.2(SHIELD2) J5.3(SHIELD1) J5.4(SHIELD3) J5.5(SHIELD4) J6.5(GND) J9.3(A2) J9.5(A3) J11.3(A2) J11.5(A3) J16.2(B1) J17.2(B1) J19.2 J26.2 L2.2 L4.2 Q1.2(EMITTER) Q2.2(EMITTER) R14.2 R23.2 R39.2 R44.2 R47.2 R51.2 R60.2 R65.2 R67.3(B) R79.2 R81.2 R85.2 R505.2 R506.2 SH18.2 SH19.2 SW3.2(S2) SW4.2(S2) SW6.1(S1) TP2.1(PIN1) TP22.1(PIN1) TP31.1(PIN1) TP36.1(PIN1) TVS1.2(A2) TVS2.2(A2) U1.2(A2) U2.2(A2) U4.7(GND) U4.9(EP) U5.2(GND) U6.2(A2) U7.2(VSS1) U7.8(VSSA) U7.33(EPAD) U8.3(DIR) U8.4(GND) U9.3(RSVD1) U9.5(GND1) U9.12(GND2) U9.13(RSVD2) U10.2(GND) U11.2(GND) U12.7(GND) U12.15(EXP) U13.2(GND) U14.2(GND) U15.2(GND) U16.2(GND) U17.1(GND) U18.13(DCDC_GND) U18.26(VSSA) U18.49(GND1) U18.50(GND2) U18.51(GND3) U18.52(GND4) U18.53(GND5) U18.54(GND6) U18.55(GND7) U18.56(GND8) U18.57(GND9) U18.58(GND10) U18.59(GND11) U18.60(GND12) U18.61(GND13) U18.62(GND14) U18.63(GND15) U18.64(GND16) U500.4(GND) X1.2 Y1.2 Y1.4 Z1.2(GND/DC_FEED) Z1.5(GND)
P3V3: C48.1 C510.1 J3.4(B2) J3.8(B4) J8.1 J9.1(A1) J15.1 J18.2(B1) J20.1 J21.1 R17.1 R26.1 R78.1 R508.1 R509.1 SH3.1 SH500.2 SH502.2 SH503.2 TP534.1(PIN1) U12.1(VCCA) U12.8(OE)
P3V3_BATT: BT500.1(POS1) BT500.2(POS2) C43.1 J27.2
P3V3_BRD: C6.1 C507.1 C508.1 C519.1 J8.2 R13.1 R16.1 R20.1 R22.2 R24.1 R29.1 R507.1 R510.1 R513.1 TP518.1(PIN1) U4.6(VCC) U9.1(VDDIO) U9.14(VDD)
P3V3_LED: C49.1 LED1.A(ANODE) LED2.A(ANODE) LED3.A(ANODE) LED4.A(ANODE) LED5.A(ANODE) R82.1 SH503.1 TP544.1(PIN1)
P3V3_LED_PWR: J20.2 LED6.A(ANODE) TP536.1(PIN1)
P3V3_SDA: C31.1 C501.1 C502.1 C504.1 C505.1 C509.1 C513.1 C514.1 C516.1 C518.1 C521.1 C523.1 J11.1(A1) R10.1 R19.1 R33.1 R34.2 R37.1 R38.1 R49.1 R59.1 R63.1 R64.1 R501.2 R503.1 SH501.1 U5.1(VCCA) U7.1(VDD1) U7.7(VDDA) U7.11(VBAT) U8.7(VCCA) U11.5(VCC) U13.1(VCCA) U14.1(VCCA) U15.1(VCCA) U16.1(VCCA) U500.1(VCCA)
P3V3_VREG: C27.1 D7.A U17.2(VOUT) U17.4(TAB)
P5V0_SDA_USB_CONN_VBUS: J6.1(VBUS) L1.1 TP513.1(PIN1) U6.1(A1)
P5V_LDO_OUT: C53.1 D10.A J26.3
P5V_SDA: C3.1 C13.1 C21.1 L1.2 R40.1 R46.1 R504.1 U7.6(VREGIN) U10.1(VIN)
P5V_SDA_PSW: D3.A D4.A U10.6(VOUT)
P5V_USB: C512.1 D4.C D5.A D10.C J3.10(B5) U12.14(VCCB)
VDD_1P8: J22.5(A3) U18.14(VDD_1P8)
VDD_1P8F: C55.1 L5.2 U18.27(VREFH) U18.28(VDDA)
VDD_1P45: C45.1 L6.1 U18.15(VDD_1P45)
VDD_1P45F: C54.1 C525.1 C526.1 C527.1 J22.4(B2) L6.2 U18.31(VDD_XTAL) U18.32(VDD_RF2) U18.35(VDD_RF1)
ADC0_SE0/BATTERY_MONITORING: R78.2 SH26.1 U18.24(ADC0_DP0/CMP0_IN0)
ADC0_SE1/POT: C32.1 R67.2(WIPER) SH27.1 TP532.1(PIN1) U18.25(ADC0_DM0/CMP0_IN1)
BUZZER: R12.1 SH10.1 SH22.2 U18.19(PTB3/ADC0_SE2/CMP0_IN4/CLKOUT/TPM1_CH1/RTC_CLKOUT/ERCLK32K)
BYP_FXOS8700CQ: C22.1 U9.2(BYP)
CMT: R80.1 SH29.1 TP535.1(PIN1) U18.17(PTB1/ADC0_SE1/CMP0_IN5/I2C0_SDA/LPTMR0_ALT1/TPM0_CH2/CMT_IRO)
COM: R511.2 SH31.1 U18.16(PTB0/I2C0_SCL/CMP0_OUT/TPM0_CH1/CLKOUT)
CRST_FXOS8700CQ: C11.1 U9.8(CRST)
D7: R5.1 U12.10(B4)
D8: R4.1 U12.11(B3)
D9: R3.1 U12.12(B2)
D10: R8.1 U12.13(B1)
DCDC_CFG: J17.1(A1) J17.3(A2) U18.9(DCDC_CFG)
DCDC_LP: J17.5(A3) L3.1 U18.11(DCDC_LP)
ELEC_IN1: SH15.1 SW2.1 TVS1.1(A1) U18.4(PTA16/TSI0_CH10/SPI1_SOUT/TPM0_CH0)
ELEC_IN2: SH14.1 SW1.1 TVS2.1(A1) U18.5(PTA17/TSI0_CH11/SPI1_SIN/TPM_CLKIN1)
EXTAL_32M: C44.1 U18.29(EXTAL_32M) Y1.1
I2C1_SCL: R42.2 R54.2 R509.2 TP20.1(PIN1) U18.38(PTC2/TSI0_CH14/TX_SWITCH/I2C1_SCL/UART0_RX/CMT_IRO/DTM_RX)
I2C1_SDA: R30.2 R45.1 R508.2 TP19.1(PIN1) U18.39(PTC3/TSI0_CH15/RX_SWITCH/I2C1_SDA/UART0_TX/DTM_TX)
I2C_SCL_FXOS8700CQ: R42.1 U9.4(SCL/SCLK)
I2C_SDA_FXOS8700CQ: R30.1 U9.6(SDA/MOSI)
INT1_COMBO: R7.2 R68.2 R510.2 SH11.1
INT1_COMBO_R: R7.1 U9.11(INT1)
INT2_COMBO: R18.2 R513.2 TP14.1(PIN1)
INT2_COMBO_R: R18.1 U9.9(INT2)
J_VDD_1P8F: C39.1 C524.1 C528.1 C529.1 C530.1 J18.4(B2) J22.3(A2) L5.1 U18.20(VDD_0) U18.44(VDD_1/VDD)
KW40_SWD_CLK: J12.2 SH8.1 TP506.1(PIN1) U18.2(PTA1/SWD_CLK/TSI0_CH9/TPM1_CH1)
LVLRST_EN: R501.1 U500.5(OE)
MIC2005_CSLEW: C13.2 U10.5(CSLEW)
P5-9V_VIN: C50.1 C51.1 C52.1 D6.A J3.16(B8) J26.1
P5-9V_VIN_VR: D3.C D5.C D6.C J33.2
POWER_EN: R41.1 U7.31(ADC0_SE7B/PTD6/SPI0_PCS3/UART0_RX/FTM0_CH6/FTM0_FLT0/LLWU_P15)
PSWITCH: J16.1(A1) J16.3(A2) J16.5(A3) SW5.1(S1) U18.8(PSWITCH)
PTB16: R71.1 SH28.1
PTB16/XTAL_32K: R71.2 R74.1 U18.21(PTB16/EXTAL32K/I2C1_SCL/TPM2_CH0)
PTB17: R76.2 SH25.1
PTB17/EXTAL_32K: R76.1 R77.1 U18.22(PTB17/XTAL32K/I2C1_SDA/TPM2_CH1)
PTB18: SH33.1 U18.23(PTB18/DAC0_OUT/ADC0_SE4/CMP0_IN2/I2C1_SCL/TPM_CLKIN0/TPM0_CH0/N\M\I\)
PTC0: R62.2 R88.2 TP542.1(PIN1) U18.36(PTC0/ANT_A/I2C0_SCL/U\A\R\T\0\_\C\T\S\/TPM0_CH1)
PTC1: R57.2 R87.1 TP540.1(PIN1) U18.37(PTC1/ANT_B/I2C0_SDA/U\A\R\T\0\_\R\T\S\/TPM0_CH2/BLE_ACTIVE)
PTC4: R53.2 R56.2 SH20.2 SH24.1 TP543.1(PIN1) U18.40(PTC4/TSI0_CH0/EXTRG_IN/U\A\R\T\0\_\C\T\S\/TPM1_CH0)
PTC5: R48.2 R52.2 SH23.2 SH30.1 TP541.1(PIN1) U18.41(PTC5/TSI0_CH1/LPTMR0_ALT2/U\A\R\T\0\_\R\T\S\/TPM1_CH1)
RF_50: C33.1 C34.1 C40.1 L4.1 Z1.1(UNBAL)
RF_ANT: ANT1.1(SIGNAL) C40.2
RF_N: R70.1 U18.33(RF_N)
RF_P: R69.1 U18.34(RF_P)
RF_SMA: C34.2 J5.1(CENTER)
RST_FXOS8700CQ: R32.1 R506.1 U9.16(RST)
RST_TGTMCU_B: D1.C(CATHODE) J3.6(B3) J9.10(B5) J24.3 R32.2 R500.2 R502.2 TP519.1(PIN1) U18.3(PTA2/R\E\S\E\T\/TMP0_CH3) U500.7(B1)
SA0_FXOS8700CQ: R29.2 SH19.1 U9.7(SA0/MISO)
SA1_FXOS8700CQ: R13.2 SH18.1 U9.10(SA1/C\S\)
SDA_CTS_EN: R37.2 R39.1 U13.5(DIR)
SDA_EXTAL: C15.1 U7.17(EXTAL0/PTA18/FTM0_FLT2/FTM_CLKIN0) X1.3
SDA_JTAG_TCLK: J11.4(B2) U7.12(JTAG_TCLK/SWD_CLK/EZP_CLK/TSI0_CH1/PTA0/U\A\R\T\0\_\C\T\S\/U\A\R\T\0\_\C\O\L\/FTM0_CH5)
SDA_JTAG_TDI: J11.8(B4) U7.13(JTAG_TDI/EZP_DI/TSI0_CH2/PTA1/UART0_RX/FTM0_CH6)
SDA_JTAG_TDO: J11.6(B3) U7.14(JTAG_TDO/TRACE_SWO/EZP_DO/TSI0_CH3/PTA2/UART0_TX/FTM0_CH7)
SDA_JTAG_TMS: J11.2(B1) R63.2 U7.15(JTAG_TMS/SWD_DIO/TSI0_CH4/PTA3/U\A\R\T\0\_\R\T\S\/FTM0_CH0)
SDA_LED: D2.C(CATHODE) TP507.1(PIN1) U7.29(PTD4/SPI0_PCS1/U\A\R\T\0\_\R\T\S\/FTM0_CH4/EWM_IN/LLWU_P14)
SDA_LED_R: D2.A(ANODE) R10.2
SDA_RST: J11.10(B5) R46.2 R47.1 TP524.1(PIN1) U7.19(R\E\S\E\T\)
SDA_RST_LED: D1.A(ANODE) R1.2
SDA_RST_TGTMCU_B: J25.2 U7.21(ADC0_SE9/TSI0_CH6/PTB1/I2C0_SDA/FTM1_CH1/FTM1_QD_PHB)
SDA_RST_TGTMCU_J_B: J24.1 J25.1 R502.1 R503.2 U500.2(A1)
SDA_RTS_EN: R49.2 R51.1 U14.5(DIR)
SDA_RX_EN: R19.2 R23.1 U5.5(DIR)
SDA_SPI0_SCK: TP529.1(PIN1) U7.26(PTC5/SPI0_SCK/LPTMR0_ALT2/I2S0_RXD0/CMP0_OUT/LLWU_P9) U16.3(A)
SDA_SPI0_SIN: TP515.1(PIN1) U7.28(CMP0_IN1/PTC7/SPI0_SIN/USB_SOF_OUT/I2S0_RX_FS) U8.5(2A)
SDA_SPI0_SOUT: TP528.1(PIN1) U7.27(CMP0_IN0/PTC6/SPI0_SOUT/PDB0_EXTRG/I2S0_RX_BCLK/I2S0_MCLK/LLWU_P10) U15.3(A)
SDA_SWD_EN: R50.1 R66.1 U11.6(Y\2\)
SDA_SWD_EN_B: R31.2 U7.16(N\M\I\/E\Z\P\_\C\S\/TSI0_CH5/PTA4/FTM0_CH1/LLWU_P3)
SDA_SWD_EN_B_R: R31.1 R38.2 U11.1(A1)
SDA_SWD_EN_R: R64.2 R65.1 R66.2 U16.5(DIR)
SDA_SWD_OE: R36.1 R61.1 U11.4(Y\1\)
SDA_SWD_OE_B: R35.2 U7.20(ADC0_SE8/TSI0_CH0/PTB0/I2C0_SCL/FTM1_CH0/FTM1_QD_PHA/LLWU_P5)
SDA_SWD_OE_B_R: R34.1 R35.1 U11.3(A2)
SDA_SWD_OE_R: R59.2 R60.1 R61.2 U15.5(DIR)
SDA_USB_DN: R25.2 U7.4(USB0_DM)
SDA_USB_DP: R21.2 U7.3(USB0_DP)
SDA_USB_P5V_SENSE: R504.2 R505.1 TP510.1(PIN1) U7.30(ADC0_SE6B/PTD5/SPI0_PCS2/U\A\R\T\0\_\C\T\S\/U\A\R\T\0\_\C\O\L\/FTM0_CH5/E\W\M\_\O\U\T\)
SDA_VOUT33: C506.1 SH501.2 SH502.1 U7.5(VOUT33)
SDA_XTAL: C10.1 U7.18(XTAL0/PTA19/FTM1_FLT0/FTM_CLKIN1/LPTMR0_ALT1) X1.1
SPI_CLK: R16.2 SH4.1 TP504.1(PIN1) U4.2(SCK) U18.45(PTC16/TSI0_CH4/SPI0_SCK/I2C0_SDA/U\A\R\T\0\_\R\T\S\/TPM0_CH3)
SPI_SIN: J28.2 R84.2 TP508.1(PIN1) U4.8(SO)
SPI_SOUT: J29.1 R83.2 TP509.1(PIN1) U4.1(SI)
SPI_SS: R24.2 SH7.1 TP516.1(PIN1) U4.4(C\S\) U18.48(PTC19/TSI0_CH7/SPI0_PCS0/I2C0_SCL/U\A\R\T\0\_\C\T\S\/BLE_ACTIVE)
SW1_RST_B: C1.1 J24.2 SW6.2(S2)
SW3: C9.1 R26.2 SH12.1 SW3.1(S1) TP503.1(PIN1) U18.7(PTA19/TSI0_CH13/SPI1_PCS0/TPM2_CH1)
SW4: C2.1 R17.2 SH13.1 SW4.1(S1) TP502.1(PIN1) U18.6(PTA18/TSI0_CH12/SPI1_SCK/TPM2_CH0)
SWD_CLK_TGTMCU: J9.4(B2) J12.1 J14.2 TP523.1(PIN1)
SWD_CLK_TGTMCU_BUF: J14.1 U16.4(B)
SWD_DIO_TGTMCU: J9.2(B1) J13.2 SH9.1 SH21.2 TP505.1(PIN1) U18.1(PTA0/SWD_DIO/TSI0_CH8/SPI0_PCS1/TPM1_CH0)
SWD_DIO_TGTMCU_BUF: J13.1 U8.2(2B) U15.4(B)
TC_EXTAL_TP: TP521.1(PIN1) U7.10(EXTAL32)
TC_XTAL_TP: TP520.1(PIN1) U7.9(XTAL32)
TP_2102_A: TP501.1(PIN1) U500.3(A2)
TP_2102_B: TP500.1(PIN1) U500.6(B2)
UART0_CTS_TGTMCU: R43.2 R52.1
UART0_RTS_TGTMCU: R55.2 R56.1
UART0_RX_TGTMCU: J30.2 R27.2 U18.42(PTC6/TSI0_CH2/I2C1_SCL/UART0_RX/TPM2_CH0)
UART0_TX_TGTMCU: J31.1 R28.2 U18.43(PTC7/TSI0_CH3/SPI0_PCS2/I2C1_SDA/UART0_TX/TPM2_CH1)
UART1_CTS_TGTMCU_BUF: R43.1 U13.4(B)
UART1_CTS_TGTMCU_R: R36.2 TP522.1(PIN1) U7.23(ADC0_SE4B/CMP1_IN0/TSI0_CH15/PTC2/SPI0_PCS2/U\A\R\T\1\_\C\T\S\/FTM0_CH1/I2S0_TX_FS) U13.3(A)
UART1_RTS_TGTMCU_BUF: R55.1 U14.4(B)
UART1_RTS_TGTMCU_R: R50.2 TP525.1(PIN1) U7.22(ADC0_SE15/TSI0_CH14/PTC1/SPI0_PCS3/U\A\R\T\1\_\R\T\S\/FTM0_CH0/I2S0_TXD0/LLWU_P6) U14.3(A)
UART1_RX_TGTMCU_BUF: R27.1 U5.4(B)
UART1_RX_TGTMCU_R: TP514.1(PIN1) U5.3(A) U7.25(PTC4/SPI0_PCS0/UART1_TX/FTM0_CH3/CMP1_OUT/LLWU_P8)
UART1_TX_TGTMCU_BUF: R28.1 U8.1(1B)
UART1_TX_TGTMCU_R: TP517.1(PIN1) U7.24(CMP1_IN1/PTC3/SPI0_PCS1/UART1_RX/FTM0_CH2/I2S0_TX_BCLK/LLWU_P7) U8.6(1A)
V_BATT: D7.C D8.C J15.3 J18.1(A1) R72.1 R73.2 R75.2 TP30.1(PIN1)
V_MCU: J21.2 J22.1(A1) J22.2(B1) TP533.1(PIN1)
V_TGTMCU: C500.1 C503.1 C511.1 C515.1 C517.1 C520.1 C522.1 R1.1 R500.1 SH500.1 U5.6(VCCB) U8.8(VCCB) U13.6(VCCB) U14.6(VCCB) U15.6(VCCB) U16.6(VCCB) U500.8(VCCB)
VDCDC_IN: C531.1 J16.4(B2) J17.4(B2) J17.6(B3) R72.2 SW5.2(S2) U18.10(VDCDC_IN)
VTRG_EN: R40.2 R41.2 R44.1 U10.3(ENABLE)
VTRG_FAULT_B: R33.2 TP511.1(PIN1) U7.32(PTD7/CMT_IRO/UART0_TX/FTM0_CH7/FTM0_FLT1) U10.4(F\A\U\L\T\)
XTAL_32M: C41.1 U18.30(XTAL_32M) Y1.3
N20064946: J3.2(B1) SH24.2
N20065027: J4.11(A6) SH33.2
N20065031: J4.9(A5) SH31.2
N20065043: J4.3(A2) SH27.2
N20065047: J4.1(A1) SH26.2
N20092069: J1.16(B8) R5.2 SH10.2
N20092076: J1.14(B7) SH11.2
N20092083: J1.12(B6) SH12.2
N20092090: J1.10(B5) SH13.2
N20092097: J1.8(B4) SH14.2
N20092104: J1.6(B3) SH15.2
N20092111: J1.4(B2) J31.2
N20092118: J1.2(B1) J30.1
N20113921: J2.6(B3) R8.2 SH7.2
N20113927: J2.12(B6) SH4.2
N20113929: J2.8(B4) J28.1
N20113931: J2.10(B5) J29.2
N20113933: J2.4(B2) R3.2 SH8.2
N20113935: J2.2(B1) R4.2 SH9.2
N20114060: J2.16(B8) SH3.2
N20114116: J2.18(B9) R87.2
N20184312: J4.2(B1) SH25.2
N20184318: J4.4(B2) SH28.2
N20184324: J4.6(B3) SH29.2
N20184330: J4.8(B4) SH30.2
N20184336: J4.10(B5) R45.2
N20184342: J4.12(B6) R54.1
N20299169: J6.2(D-) R25.1 TP4.1(PIN1) U2.1(A1)
N20299247: J6.3(D+) R21.1 TP3.1(PIN1) U1.1(A1)
N20456851: R20.2 U4.3(R\E\S\E\T\)
N20492386: J2.20(B10) R88.1
N20531142: LED5.C(CATHODE) R511.1 TP531.1(PIN1)
N20531179: LED6.C(CATHODE) R81.1 TP537.1(PIN1)
N20532222: C46.1 R74.2 Y2.1
N20532224: C47.1 R77.2 Y2.2
N20553853: LED4.C(CATHODE) R62.1 TP28.1(PIN1)
N20553861: LED2.C(CATHODE) R53.1 TP25.1(PIN1)
N20553879: LED1.C(CATHODE) R48.1 TP21.1(PIN1)
N20553881: LED3.C(CATHODE) R57.1 TP26.1(PIN1)
N20693809: R68.1 U18.18(PTB2/ADC0_SE3/CMP0_IN3/TPM1_CH0)
N20693837: L3.2 U18.12(DCDC_LN)
N20693945: R84.1 U18.47(PTC18/TSI0_CH6/SPI0_SIN/UART0_TX/DTM_TX)
N20693947: R83.1 U18.46(PTC17/TSI0_CH5/SPI0_SOUT/UART0_RX/DTM_RX)
N20694234: C42.2 R70.2 Z1.4(BAL4)
N20694236: C42.1 R69.2 Z1.3(BAL3)
N20694515: J16.6(B3) R85.1
N20696372: D9.A J19.1
N20696388: D9.C J23.2
N20696455: C25.1 J23.1 J33.1 TP530.1(PIN1) U17.3(VIN)
N20743134: BZ500.2 Q1.3(COLLECTOR) R512.2
N20743140: Q1.1(BASE) R12.2 R14.1
N20743144: BZ500.1 R507.2 R512.1 TP526.1(PIN1)
N20744082: D11.A(ANODE) R82.2 TP538.1(PIN1)
N20744086: Q2.1(BASE) R79.1 R80.2
N20744096: D11.C(CATHODE) Q2.3(COLLECTOR) TP539.1(PIN1)
N20748907: J15.2 R67.1(A)
N20755274: SH22.1 U12.5(A4)
N20755276: SH20.1 U12.3(A2)
N20755278: SH21.1 U12.4(A3)
N20755280: SH23.1 U12.2(A1)
N20771285: J23.3 R75.1
N20771753: D8.A J27.1 R73.1 TP29.1(PIN1)
N20845596: R22.1 U4.5(W\P\)
N20885985: J6.6(SHELL1) J6.7(SHELL2) J6.8(SHELL3) J6.9(SHELL4) J6.10(SHELL5) L2.1

Pads without a net: J1 1 3 5 7 9 11 13 15; J2 1 3 5 7 9 11 13 15 17 19; J3 1 3 5 7 9 11 13 15; J4 5 7; J6 4; J9 6 7 8 9; J11 7 9; J18 3; J22 6; U9 15; U12 6 9; Z1 6

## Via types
v1: diameter 0.508, hole 0.254, TOP to BOTTOM, 566 vias
v2: diameter 0.559, hole 0.305, TOP to BOTTOM, 2 vias
v3: diameter 0.457, hole 0.203, TOP to BOTTOM, 283 vias

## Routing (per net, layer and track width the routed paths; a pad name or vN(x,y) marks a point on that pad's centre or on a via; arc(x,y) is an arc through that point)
GND: length 327.7
  TOP w0.203: U9.5 v1(55.42,31.57) ; U9.3 v1(54.42,31.6) ; U9.13 v1(53.42,39.92) ; U9.12 v1(53.92,40.75)
  TOP w0.254: C44.2 54.21,14.17 ; U11.2 v1(23.08,31.39) ; U7.2 18.22,39.71 v1(19.47,38.46) 17.72,36.7 U7.8 ; Y1.4 55.17,12.94 ; 53.1,15.57 U18.26 ; 42.92,9.28 C46.2 43.78,10.15 ; C41.2 55.45,14.2 ; 44.63,8.95 C47.2 43.84,8.62
  TOP w0.279: v1(46.47,18.47) 46.55,18.47 U18.13
  TOP w0.305: U8.3 31.02,37.25 v1(31.25,37.49) ; U12.7 v1(43.57,31.19) ; U8.4 v1(29.93,38.13) ; U5.2 v1(28.89,39.4) ; U7.2 v1(16.2,39.71) ; U13.2 v1(28.64,31.55) ; U7.8 v1(17.07,36.11) ; U14.2 v1(28.74,28.63) ; U16.2 v1(28.92,22.3) ; U15.2 v1(28.79,25.43)
  TOP w0.356: J6.5 5.58,43.57 ; 61.41,16.09 Z1.2 ; v3(58.07,12.74) Z1.5
  TOP w0.381: 43.78,9.64 C46.2 43.27,9.13 ; 43.59,8.31 TP36.1 43.01,8.88 ; 43.17,15.67 C55.2 ; C47.2 44.3,9.12
  TOP w0.406: 24.67,37.36 C10.2 23.91,37.36 v1(23.41,36.86) 23.86,36.4 C15.2 24.63,36.4 ; X1.2 25.01,36.82
  TOP w0.508: 23.46,21.54 C31.2 ; C31.2 v1(22.69,22.05) ; C31.2 23.46,22.56 ; 46.77,41.15 R14.2 ; R14.2 46.27,41.66 ; R14.2 47.28,41.66 ; R23.2 v1(33.36,38.38) ; 26.49,49.81 J2.14 ; J2.14 25.48,50.83 ; J2.14 26.49,51.84 ; J2.14 27.51,50.83 ; 60.66,21.62 TVS2.2 61.61,21.62 ; 4.85,49.72 SW6.1 ; SW6.1 v1(3.77,50.67) ; SW6.1 5.57,50.67 ; 43.05,32.72 U12.15 40.64,32.72 ; 40.6,3.58 J3.12 41.62,2.57 ; C43.2 v1(7.49,18.4) ; 38.62,15.51 J17.2 37.68,14.57 ; R47.2 v1(25.13,31.29) ; R47.2 25.13,29.97 ; R47.2 25.64,30.48 ; J9.5 37.82,32.26 ; U4.9 39.64,42.7 ; U4.9 41.63,40.41 ; U4.9 37.64,40.41 ; v1(8.49,40.31) U2.2 9.13,41.1 ; 44.18,31.97 U12.7 43.57,32.3 ; 8.49,43.37 U1.2 9.13,42.82 ; 63.95,37.74 C9.2 63.44,38.25 ; U4.7 v1(43.7,41.05) ; U4.7 42.49,40.55 ; U4.7 42.49,41.54 ; 13.51,33.45 U10.2 C21.2 v1(11.26,32.51) ; C51.2 9.69,7.98 ; C51.2 8.93,7.34 ; C51.2 10.45,7.34 ; R81.2 12.99,7.9 ; R81.2 12.99,6.88 ; R81.2 12.48,7.39 ; J9.3 37.82,30.99 ; 53.25,28.63 C22.2 ; C22.2 53.76,29.13 ; C22.2 52.74,29.13 ; 13.3,30.05 R44.2 ; R44.2 14.31,30.05 ; R44.2 v1(13.8,29.24) ; 33.49,22.81 R65.2 34,22.3 ; v1(59.93,39.76) 59.93,39.79 59.93,39.8 C2.2 ; C50.2 7.91,7.98 ; C50.2 7.15,7.34 ; C50.2 8.67,7.34 ; v1(32.96,29.31) 33.31,28.96 R51.2 33.82,28.63 ; 33.72,31.55 R39.2 v1(33.21,32.36) ; TP2.1 64.94,46.29 ; TP2.1 64.94,45.15 ; TP2.1 65.51,45.72 ; Q1.2 48.95,41.2 ; Q1.2 48.15,40.63 ; Q1.2 48.95,40.06 ; C1.2 v1(7.89,46.46) ; C1.2 7.38,47.24 ; C1.2 7.89,47.75 ; L4.2 v3(63.84,17.04) ; 7.09,22.79 U17.1 6.3,24.08 ; C25.2 7.18,25.91 ; C25.2 7.18,24.38 ; C25.2 7.81,25.15 ; 0.71,7.54 C53.2 ; C53.2 2.24,7.54 ; C53.2 1.47,8.17 ; 9.32,29.11 TP22.1 ; TP22.1 9.89,29.68 ; TP22.1 10.47,29.11 ; SW4.2 66.48,41.16 ; SW4.2 66.48,39.26 ; SW4.2 65.75,40.21 ; SW4.2 67.2,40.21 ; C44.2 54.72,14.63 ; 66.64,33.09 v3(66.64,33.07) ; J11.5 25.15,26.21 ; 61.15,38.23 SH19.2 60.13,38.23 ; 19.13,5.46 Q2.2 ; Q2.2 19.7,4.66 ; Q2.2 20.49,5.46 v1(20.56,5.39) ; Q2.2 19.7,6.26 ; 40.17,11.53 C54.2 39.54,12.29 ; 44.92,38.25 C6.2 45.43,38.76 ; 39.53,13.79 C45.2 40.17,14.55 ; 5.89,36.41 L2.2 ; L2.2 5.89,37.61 ; L2.2 6.39,37.01 ; U6.2 7.67,38.14 ; U6.2 7.12,37.49 ; U6.2 v1(6.17,38.14) ; 5.85,7.8 6.87,7.8 ; 5.85,7.8 5.85,8.81 ; 5.85,7.8 4.84,7.8 ; SH18.2 55.94,42.09 v1(55.6,42.43) ; 58.53,38.23 C11.2 59.8,38.23 ; 56.16,10.55 Y1.2 55.27,11.34 ; 55.45,15.16 C41.2 54.95,14.65 ; R60.2 v1(33.36,26.24) ; R85.2 v1(24.83,13.56) ; 6.04,3.48 J26.2 ; J26.2 7,2.53 ; J26.2 7,4.43 ; Y1.4 53.96,13.72 ; 39.61,15.67 C39.2 40.37,15.04 ; v3(62.7,17.06) C33.2 ; 10.98,40.94 C3.2 ; 7.71,8.8 C32.2 7.2,9.31 ; C52.2 12.23,7.34 ; C52.2 10.71,7.34 ; C52.2 11.47,7.98 ; SW3.2 66.48,35.22 ; SW3.2 67.2,34.26 ; SW3.2 66.48,33.31 ; SW3.2 65.75,34.26 ; 58.99,31 TVS1.2 ; TVS1.2 v1(58.99,32.18) ; TVS1.2 58.51,31.47 ; J3.14 43.14,3.58 ; J3.14 44.16,2.57 ; J3.14 42.13,2.57 ; 43.8,15.04 C55.2 ; 9.12,23.84 C27.2 9.88,23.21 ; 9.38,9.86 J19.2 10.34,8.9 ; J11.3 25.15,24.94
  TOP w0.635: C48.2 v1(26.89,8.57)
  GND w0.381: 37.68,14.57 J17.2 ; J17.2 37.68,16.45 ; J17.2 38.62,15.51 ; J17.2 36.74,15.51 ; 30.75,10.64 TP31.1 ; TP31.1 30.75,13.34 ; TP31.1 32.09,11.99 ; TP31.1 29.4,11.99 ; J16.2 31.59,15.51 ; J16.2 29.7,15.51 ; J16.2 30.65,14.57 ; J16.2 30.65,16.45 ; 9.38,9.86 J19.2 ; J19.2 10.34,8.9 ; J19.2 11.29,9.86 ; J19.2 10.34,10.81 ; 25.48,50.83 J2.14 ; J2.14 26.49,51.84 ; J2.14 27.51,50.83 ; J2.14 26.49,49.81 ; 4.84,7.8 5.85,7.8 ; 5.85,7.8 5.85,6.78 ; 5.85,7.8 6.87,7.8 ; 5.85,7.8 5.85,8.81 ; J9.5 37.82,32.26 ; 6.04,3.48 J26.2 ; J26.2 7.95,3.48 ; J26.2 7,2.53 ; J26.2 7,4.43 ; 42.13,2.57 J3.14 ; J3.14 43.14,3.58 ; J3.14 43.14,1.55 ; J3.14 44.16,2.57 ; J9.3 37.82,30.99 ; J3.12 40.6,3.58 ; J3.12 39.59,2.57 ; J3.12 41.62,2.57 ; J3.12 40.6,1.55 ; J11.5 25.15,26.21 ; J11.3 25.15,24.94
  INT_1 w0.381: J3.14 43.14,3.58 ; J3.14 42.13,2.57 ; J3.14 43.14,1.55 ; J3.14 44.16,2.57 ; J2.14 26.49,51.84 ; J2.14 26.49,49.81 ; J2.14 27.51,50.83 ; J2.14 25.48,50.83 ; 29.4,11.99 TP31.1 ; TP31.1 30.75,10.64 ; TP31.1 30.75,13.34 ; TP31.1 32.09,11.99 ; J26.2 7.95,3.48 ; J26.2 6.04,3.48 ; J26.2 7,2.53 ; J26.2 7,4.43 ; 10.34,8.9 J19.2 ; J19.2 10.34,10.81 ; J19.2 9.38,9.86 ; J19.2 11.29,9.86 ; J11.5 25.15,26.21 ; 5.85,7.8 6.87,7.8 ; 5.85,7.8 4.84,7.8 ; 5.85,7.8 5.85,6.78 ; 5.85,7.8 5.85,8.81 ; J3.12 40.6,3.58 ; J3.12 40.6,1.55 ; J3.12 41.62,2.57 ; J3.12 39.59,2.57 ; J11.3 25.15,24.94
  BOTTOM w0.203: U500.4 v1(5.53,48.5)
  BOTTOM w0.254: C524.2 51.38,24.28 ; C524.2 50.54,23.44 ; C524.2 51.47,23.86 ; C524.2 50.45,23.86 ; C524.2 50.96,23.35 ; C524.2 50.54,24.28 ; 54.98,20.43 C526.2 ; C526.2 54.56,21.36 ; C526.2 54.47,20.94 ; C526.2 55.41,21.36 ; C526.2 54.98,21.45 ; C526.2 55.49,20.94 ; C527.2 52.61,20.46 ; C527.2 52.1,19.95 ; C527.2 53.12,19.95 ; C527.2 53.03,20.38 ; C527.2 52.18,20.38 ; 51.39,19.24 C525.2 ; C525.2 51.48,19.66 ; C525.2 51.9,18.73 ; C525.2 51.9,19.74 ; C525.2 51.48,18.81
  BOTTOM w0.381: 42.13,2.57 J3.14 ; J3.14 43.14,3.58 ; J3.14 43.14,1.55 ; J3.14 44.16,2.57 ; 21.55,34.82 C513.2 22.06,35.33 ; C506.2 15.71,39.7 ; C501.2 9.92,48.46 ; C501.2 9.41,48.97 ; C501.2 9.41,47.95 ; 28.41,23.77 C523.2 ; C523.2 27.9,24.28 ; C523.2 28.41,24.79 ; 31.25,33.07 C515.2 ; C515.2 31.25,34.09 ; C515.2 31.76,33.58 ; C516.2 28.13,34.04 ; C516.2 27.62,33.53 ; C516.2 28.13,33.02 ; TP31.1 32.09,11.99 ; TP31.1 29.4,11.99 ; TP31.1 30.75,10.64 ; 31.41,26.95 C520.2 ; C520.2 31.92,27.46 ; C520.2 31.41,27.97 ; J11.5 25.15,26.21 ; 27.65,34.7 C514.2 ; C514.2 28.16,34.19 ; C514.2 28.16,35.2 ; 49.21,33.02 R506.2 ; R506.2 50.23,33.02 ; R506.2 49.72,32.51 ; 7.75,26.3 9.92,26.3 ; 9.92,26.3 12.09,26.3 ; 9.92,26.3 9.92,24.13 ; 9.92,26.3 9.92,28.47 ; C510.2 44.08,35.89 ; C510.2 43.57,36.4 ; C510.2 43.07,35.89 ; 27.55,29.23 C518.2 ; C518.2 27.04,29.74 ; C518.2 27.55,30.25 ; C504.2 16.22,42.44 ; C504.2 16.73,41.94 ; C504.2 15.71,41.94 ; 31.59,15.51 J16.2 30.65,14.57 ; C507.2 50.84,38.76 ; J2.14 26.49,51.84 ; J2.14 25.48,50.83 ; J2.14 27.51,50.83 ; J2.14 26.49,49.81 ; C531.2 47.89,18.23 ; C531.2 46.88,18.23 ; C531.2 47.38,17.72 ; 29.56,38.31 C505.2 29.05,38.81 ; 23.51,4.5 C49.2 ; C49.2 24.52,4.5 ; C49.2 24.02,3.99 ; 5.85,7.8 5.85,8.81 ; 5.85,7.8 4.84,7.8 ; 5.85,7.8 6.87,7.8 ; 9.49,49.55 C500.2 9.49,50.57 ; 31.36,30.15 C517.2 ; C517.2 31.36,31.17 ; C517.2 31.86,30.66 ; J9.3 37.82,30.99 ; C511.2 31.94,35.76 ; C511.2 31.94,34.75 ; C511.2 32.45,35.26 ; 40.6,1.55 J3.12 ; J3.12 39.59,2.57 ; J3.12 41.62,2.57 ; J3.12 40.6,3.58 ; C528.2 47.68,16.6 ; 37.68,14.57 J17.2 38.62,15.51 ; 27.77,27.41 C521.2 28.28,26.9 ; 38.59,34.85 C512.2 ; C512.2 39.1,34.34 ; C512.2 39.1,35.36 ; 48.83,29.62 C519.2 ; C519.2 49.34,30.12 ; C519.2 49.85,29.62 ; 17.56,43.36 R505.2 18.07,42.85 ; 7,2.53 J26.2 ; J26.2 7.95,3.48 ; J26.2 6.04,3.48 ; J26.2 7,4.43 ; J11.3 25.15,24.94 ; 31.53,23.82 C522.2 ; C522.2 32.04,24.33 ; C522.2 31.53,24.84 ; 14.11,42.47 C502.2 15.63,42.47 ; 17.16,37.95 C509.2 ; C509.2 18.17,37.95 ; C509.2 17.67,38.46 ; J19.2 10.34,10.81 ; J19.2 11.29,9.86 ; J19.2 10.34,8.9 ; J19.2 9.38,9.86 ; 46.62,15.32 C529.2 46.11,14.81 ; 48.4,13.41 C530.2 48.91,13.92 ; 21.35,6.02 R79.2 20.84,5.51 ; J9.5 37.82,32.26 ; 48.86,38.76 C508.2 ; C503.2 31.08,38.81
  BOTTOM w0.508: C530.2 v1(48.93,14.48)
  vias: v1(0.67,24.18) v1(0.67,22.45) v1(0.79,19.91) v1(0.77,18.04) v1(0.8,16.81) v1(0.8,15.93) v1(0.77,15.04) v1(0.77,10.44) v1(0.77,8.75) v1(1.16,32.88) v1(1.66,4.02) v1(1.84,50.3) v1(2.05,8.67) v1(2.81,12.01) v1(2.73,10.49) v1(2.9,51.48) v1(3.78,1.45) v1(4.2,27.3) v1(4.38,12.01) v1(4.43,10.52) v1(4.67,8.79) v1(5.77,42.74) v1(5.74,35.41) v1(5.82,0.72) v1(5.91,52.57) v1(6.02,2.21) v1(6.82,8.89) v1(6.84,1.23) v1(6.99,52.59) v1(7,27.28) v1(7.16,36.74) v1(7.41,28.85) v1(7.48,17.12) v1(7.51,15.9) v1(7.51,2.23) v1(7.92,0.69) v1(8.08,52.6) v1(8.04,35.18) v1(8.19,38.18) v1(8.87,1.23) v1(8.94,30.36) v1(8.92,28.81) v1(8.93,9.49) v1(9.1,52.6) v1(9.02,33.42) v1(9.02,31.95) v1(9.35,43.32) v1(9.68,40.2) v1(9.71,8.73) v1(9.82,49.25) v1(9.91,46.41) v1(9.93,0.7) v1(10.11,52.58) v1(10.6,8.66) v1(10.9,1.23) v1(11.05,23.41) v1(12,9.98) v1(12.33,44.76) v1(12.89,18.14) v1(12.92,19.14) v1(13.08,25.81) v1(13.07,23.64) v1(14.52,22.27) v1(14.56,19.69) v1(14.77,29.39) v1(14.8,17.53) v1(16.48,47.17) v1(17.57,52.28) v1(17.64,47.17) v1(17.69,23.75) v1(17.68,5.45) v1(17.78,45.55) v1(17.83,29.49) v1(17.87,27.22) v1(17.92,17.48) v1(18.45,3.9) v1(18.55,45.07) v1(18.58,31.24) v1(18.7,33.22) v1(19.44,10.46) v1(19.6,52.28) v1(19.55,2.09) v1(19.65,27.56) v1(19.66,26.14) v1(19.67,25.02) v1(20.18,46.99) v1(20.36,32.51) v1(20.6,6.28) v1(20.86,16.33) v1(21.42,46.85) v1(21.63,52.28) v1(21.78,28.45) v1(21.77,26.9) v1(21.95,35.98) v1(21.93,25.24) v1(21.95,24.21) v1(22.31,3.17) v1(22.76,14.7) v1(23,2.46) v1(23.16,35.66) v1(23.22,45.52) v1(23.67,52.28) v1(23.63,46.68) v1(23.61,38.74) v1(24.59,46.72) v1(25.22,43.84) v1(25.29,29.44) v1(25.23,2.53) v1(25.37,28.2) v1(25.32,26.9) v1(25.36,25.53) v1(25.37,22.91) v1(25.7,52.28) v1(25.67,4.75) v1(25.85,46.74) v1(27.05,41.37) v1(27.12,46.73) v1(27.38,24.09) v1(27.73,52.28) v1(27.73,40.78) v1(27.83,8.56) v1(28.13,22.72) v1(28.26,46.74) v1(28.74,26.46) v1(28.8,21.11) v1(29.76,52.28) v1(30.8,21.07) v1(31.79,52.28) v1(32.86,26.98) v1(33.31,33.86) v1(33.82,52.28) v1(33.97,26.89) v1(34.27,21.69) v1(34.29,20.18) v1(34.49,34.1) v1(34.47,32.09) v1(34.85,46.71) v1(35.85,52.28) v1(35.97,46.7) v1(37.17,37.76) v1(37.36,46.71) v1(37.49,27.09) v1(37.79,28.73) v1(37.88,52.28) v1(38.48,46.7) v1(39.09,37.19) v1(39.1,33.68) v1(39.29,12.42) v1(39.38,11.13) v1(39.38,9.68) v1(39.46,43.06) v1(39.92,52.28) v1(39.93,46.71) v1(40.14,32.77) v1(40.16,31.09) v1(40.33,11.23) v1(40.45,9.45) v1(40.56,43) v1(41.15,46.71) v1(41.21,23.16) v1(41.37,43.78) v1(41.9,3.81) v1(41.95,52.28) v1(42.76,23.18) v1(42.82,16.26) v1(42.95,26.1) v1(43.41,43.75) v1(43.42,32.72) v1(43.55,13) v1(43.63,48.52) v1(43.8,46.76) v1(43.98,52.28) v1(43.99,51) v1(44,37.19) v1(43.96,29.7) v1(44.18,9.47) v1(44.26,26.08) v1(44.47,3.87) v1(45.09,43.46) v1(45.15,40.79) v1(45.11,36.12) v1(45.25,34.26) v1(45.42,38.15) v1(45.47,37.17) v1(45.54,32.73) v1(45.57,28.34) v1(45.7,41.79) v1(46.01,52.28) v1(46.25,43.3) v1(46.22,15.72) v1(46.6,11.25) v1(47.11,3.85) v1(47.27,46.84) v1(47.25,40.27) v1(47.34,45.71) v1(47.47,23.21) v1(47.41,16.79) v1(48.04,52.28) v1(48.26,28.75) v1(48.85,32.13) v1(49.01,46.93) v1(49.31,41.48) v1(49.45,12.66) v1(49.96,13.57) v1(50.08,52.28) v1(50.04,46.96) v1(50.17,10.72) v1(50.28,29.74) v1(50.41,30.78) v1(50.49,26.72) v1(50.79,42.95) v1(50.85,17.42) v1(50.93,13.31) v1(51.14,31.52) v1(51.41,26.78) v1(51.4,25.46) v1(51.37,10.72) v1(51.61,46.9) v1(51.77,40.13) v1(51.88,42.44) v1(52.01,13.57) v1(52.06,1.29) v1(52.11,52.28) v1(52.16,11.9) v1(52.32,25.46) v1(52.63,46.93) v1(52.9,7.39) v1(53.57,26.8) v1(53.65,28.25) v1(53.78,24.35) v1(54.01,8.51) v1(54.14,52.28) v1(54.11,46.91) v1(54.29,29.33) v1(54.48,30.21) v1(54.65,23.05) v1(54.68,1.37) v1(54.89,14.02) v1(55.17,46.92) v1(55.33,9.48) v1(56.17,52.28) v1(56.29,7.93) v1(56.64,45.04) v1(56.74,46.94) v1(57.28,1.36) v1(57.55,21.05) v1(57.64,11.99) v1(57.85,46.95) v1(58.2,52.28) v1(58.21,7.5) v1(58.42,37.2) v1(59.19,43.35) v1(59.4,46.98) v1(59.39,35.08) v1(59.48,22.47) v1(59.51,45.55) v1(59.7,7.38) v1(59.75,1.34) v1(60.23,52.28) v1(61.07,7.4) v1(61.37,38.02) v1(61.71,36.74) v1(62.19,1.46) v1(62.27,52.28) v1(62.9,25.42) v1(62.91,26.66) v1(63.46,39.73) v1(63.44,34.74) v1(64.3,38.58) v1(64.3,37.41) v1(64.28,33.68) v1(64.97,1.39) v1(65.39,34.77) v1(71.29,52.33) v3(50.49,19.94) v3(51.2,20.65) v3(51.2,19.23) v3(51.92,21.36) v3(51.92,19.94) v3(51.92,18.52) v3(52.63,20.65) v3(52.63,19.23) v3(53.31,19.94) v3(54.98,15.62) v3(55.15,17.27) v3(57.51,14.24) v3(57.52,13.37) v3(58.13,18.39) v3(58.63,19.63) v3(58.96,17.41) v3(59.38,12.25) v3(59.61,18.12) v3(59.63,16.79) v3(59.79,19.49) v3(60.54,18.91) v3(60.57,16.59) v3(60.54,12.77) v3(61.16,12.18) v3(61.47,19.64) v3(61.49,18.19) v3(61.46,17.08) v3(61.78,12.75) v3(61.94,23.13) v3(62.48,22.21) v3(62.65,11.88) v3(62.82,10.49) v3(62.99,20.68) v3(62.94,18.96) v3(63.34,12.75) v3(63.54,19.84) v3(63.52,18.06) v3(63.75,6.59) v3(63.99,11.85) v3(64.4,43.56) v3(64.4,42.04) v3(64.4,39.85) v3(64.38,35.7) v3(64.36,20.61) v3(64.38,19.1) v3(64.36,12.75) v3(64.42,34.86) v3(64.91,6.81) v3(65.09,52.35) v3(65.03,49.77) v3(65.1,32.25) v3(65.1,18.04) v3(65.12,47.72) v3(65.16,44.32) v3(65.16,42.8) v3(65.16,39.09) v3(65.16,37.57) v3(65.16,36.04) v3(65.14,19.86) v3(65.13,16.27) v3(65.35,33.75) v3(65.38,10.25) v3(65.42,40.89) v3(65.7,12.76) v3(65.85,31.54) v3(65.87,17.24) v3(65.93,46.61) v3(65.93,45.09) v3(65.93,43.56) v3(65.93,38.33) v3(65.93,36.8) v3(65.91,32.57) v3(65.93,20.62) v3(65.93,19.1) v3(65.93,11.33) v3(65.93,5.21) v3(66.34,9.56) v3(66.54,16.33) v3(66.69,45.85) v3(66.69,44.32) v3(66.69,42.8) v3(66.64,39.04) v3(66.69,37.57) v3(66.69,36.04) v3(66.69,32.08) v3(66.69,25.98) v3(66.69,19.86) v3(66.69,18.02) v3(66.69,12.09) v3(66.69,10.57) v3(66.69,5.97) v3(66.89,27.49) v3(66.9,22.88) v3(66.85,21.37) v3(66.91,30.51) v3(66.91,29.04) v3(66.95,24.51) v3(67.32,17.26) v3(67.45,45.09) v3(67.45,43.56) v3(67.45,42.04) v3(67.45,39.85) v3(67.45,38.33) v3(67.45,36.8) v3(67.45,35.28) v3(67.45,32.84) v3(67.45,31.32) v3(67.45,29.79) v3(67.45,28.27) v3(67.45,26.75) v3(67.45,25.22) v3(67.45,23.67) v3(67.45,22.15) v3(67.45,20.62) v3(67.45,19.1) v3(67.46,12.8) v3(67.48,11.33) v3(67.48,9.8) v3(67.85,37.54) v3(67.84,36.02) v3(67.84,34.54) v3(67.84,33.65) v3(67.85,32.11) v3(67.84,30.57) v3(67.84,29.05) v3(67.84,27.53) v3(67.84,26) v3(67.84,24.48) v3(67.84,22.93) v3(67.84,21.41) v3(67.84,19.88) v3(67.83,18.04) v3(68.04,39.01) v3(68.24,45.85) v3(68.24,44.32) v3(68.24,42.8) v3(68.24,40.64) v3(68.24,12.09) v3(68.24,10.57) v3(68.97,45.09) v3(68.97,43.56) v3(68.98,12.8) v3(69,11.33) v3(69,9.8) v3(69,6.73) v3(69.17,8.34) v3(69.28,42.5) v3(69.74,45.85) v3(69.74,44.32) v3(69.76,12.09) v3(69.76,10.57) v3(69.76,9.04) v3(69.76,7.49) v3(69.94,43.35) v3(70.5,46.61) v3(70.5,45.09) v3(70.51,12.8) v3(70.52,11.33) v3(70.52,9.8) v3(70.52,8.28) v3(70.52,6.73) v3(70.78,44.12) v3(71.29,47.37) v3(71.29,45.85) v3(71.29,38.25) v3(71.29,36.73) v3(71.29,35.2) v3(71.29,33.68) v3(71.29,32.16) v3(71.29,30.61) v3(71.29,29.08) v3(71.29,27.56) v3(71.29,26.04) v3(71.29,24.51) v3(71.29,22.96) v3(71.29,21.44) v3(71.29,19.91) v3(71.29,18.39) v3(71.3,16.69) v3(71.29,12.09) v3(71.29,10.57) v3(71.29,9.04) v3(71.29,7.49) v3(71.29,5.97) v3(71.58,44.82) v3(71.77,39.9) v3(71.87,8.2) v3(71.99,11.36) v3(71.97,9.67) v3(72.02,48.13) v3(72.02,46.61) v3(72.05,39.01) v3(72.05,37.49) v3(72.05,35.97) v3(72.05,34.44) v3(72.05,32.92) v3(72.05,31.37) v3(72.05,29.85) v3(72.05,28.32) v3(72.05,26.8) v3(72.05,25.27) v3(72.05,23.75) v3(72.05,22.2) v3(72.05,20.68) v3(72.05,19.15) v3(72.08,17.62) v3(72.07,16.26) v3(72.03,12.8) v3(72.05,6.73) v3(72.05,5.21) v3(72.46,40.91) v3(72.81,48.92) v3(72.81,47.37) v3(72.81,45.85) v3(72.81,39.78) v3(72.83,38.26) v3(72.83,36.74) v3(72.83,35.21) v3(72.83,33.69) v3(72.83,32.17) v3(72.83,30.62) v3(72.83,29.09) v3(72.83,27.57) v3(72.83,26.05) v3(72.83,24.52) v3(72.83,22.97) v3(72.83,21.45) v3(72.83,19.92) v3(72.83,18.4) v3(72.85,16.67) v3(72.89,12.05) v3(72.89,9.82) v3(72.9,7.52) v3(72.81,5.97) v3(72.81,4.45) v3(72.81,2.92) v3(72.81,1.39) v3(73.23,41.58) v3(73.57,48.13) v3(73.57,46.61) v3(73.57,40.56) v3(74.25,42.16) v3(74.33,48.92) v3(74.33,47.37) v3(74.33,45.85) v3(74.33,41.33) v3(74.33,39.78) v3(75.1,49.66) v3(75.1,48.13) v3(75.1,46.61) v3(75.1,42.09) v3(75.1,40.56) v3(75.78,45.95) v3(75.86,51.97) v3(75.86,50.44) v3(75.86,47.37) v3(75.88,41.33) v3(76.62,51.21) v3(76.62,49.66) v3(76.62,46.61) v3(76.64,42.09) v3(77.3,45.95) v3(77.38,51.97) v3(77.38,50.44) v3(77.38,47.37) v3(77.41,41.33) v3(78.14,51.21) v3(78.14,49.66) v3(78.14,46.61) v3(78.17,42.09) v3(78.85,45.95) v3(78.93,50.44) v3(78.93,47.37) v3(78.93,41.33) v3(79.67,46.61) v3(79.69,42.09) v3(80.38,45.95) v3(80.45,47.37) v3(80.45,41.33)
